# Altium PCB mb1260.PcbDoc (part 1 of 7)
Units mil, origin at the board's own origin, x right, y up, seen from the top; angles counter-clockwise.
Board outline 3189.01 x 3818.89 mil, 6 copper layers (TOP, L2_GND, L3_VCC, L4_SIG, L5_GND, BOTTOM), stack 62.2 mil thick; 308 components, 287 nets, 1220 pads, 851 vias.
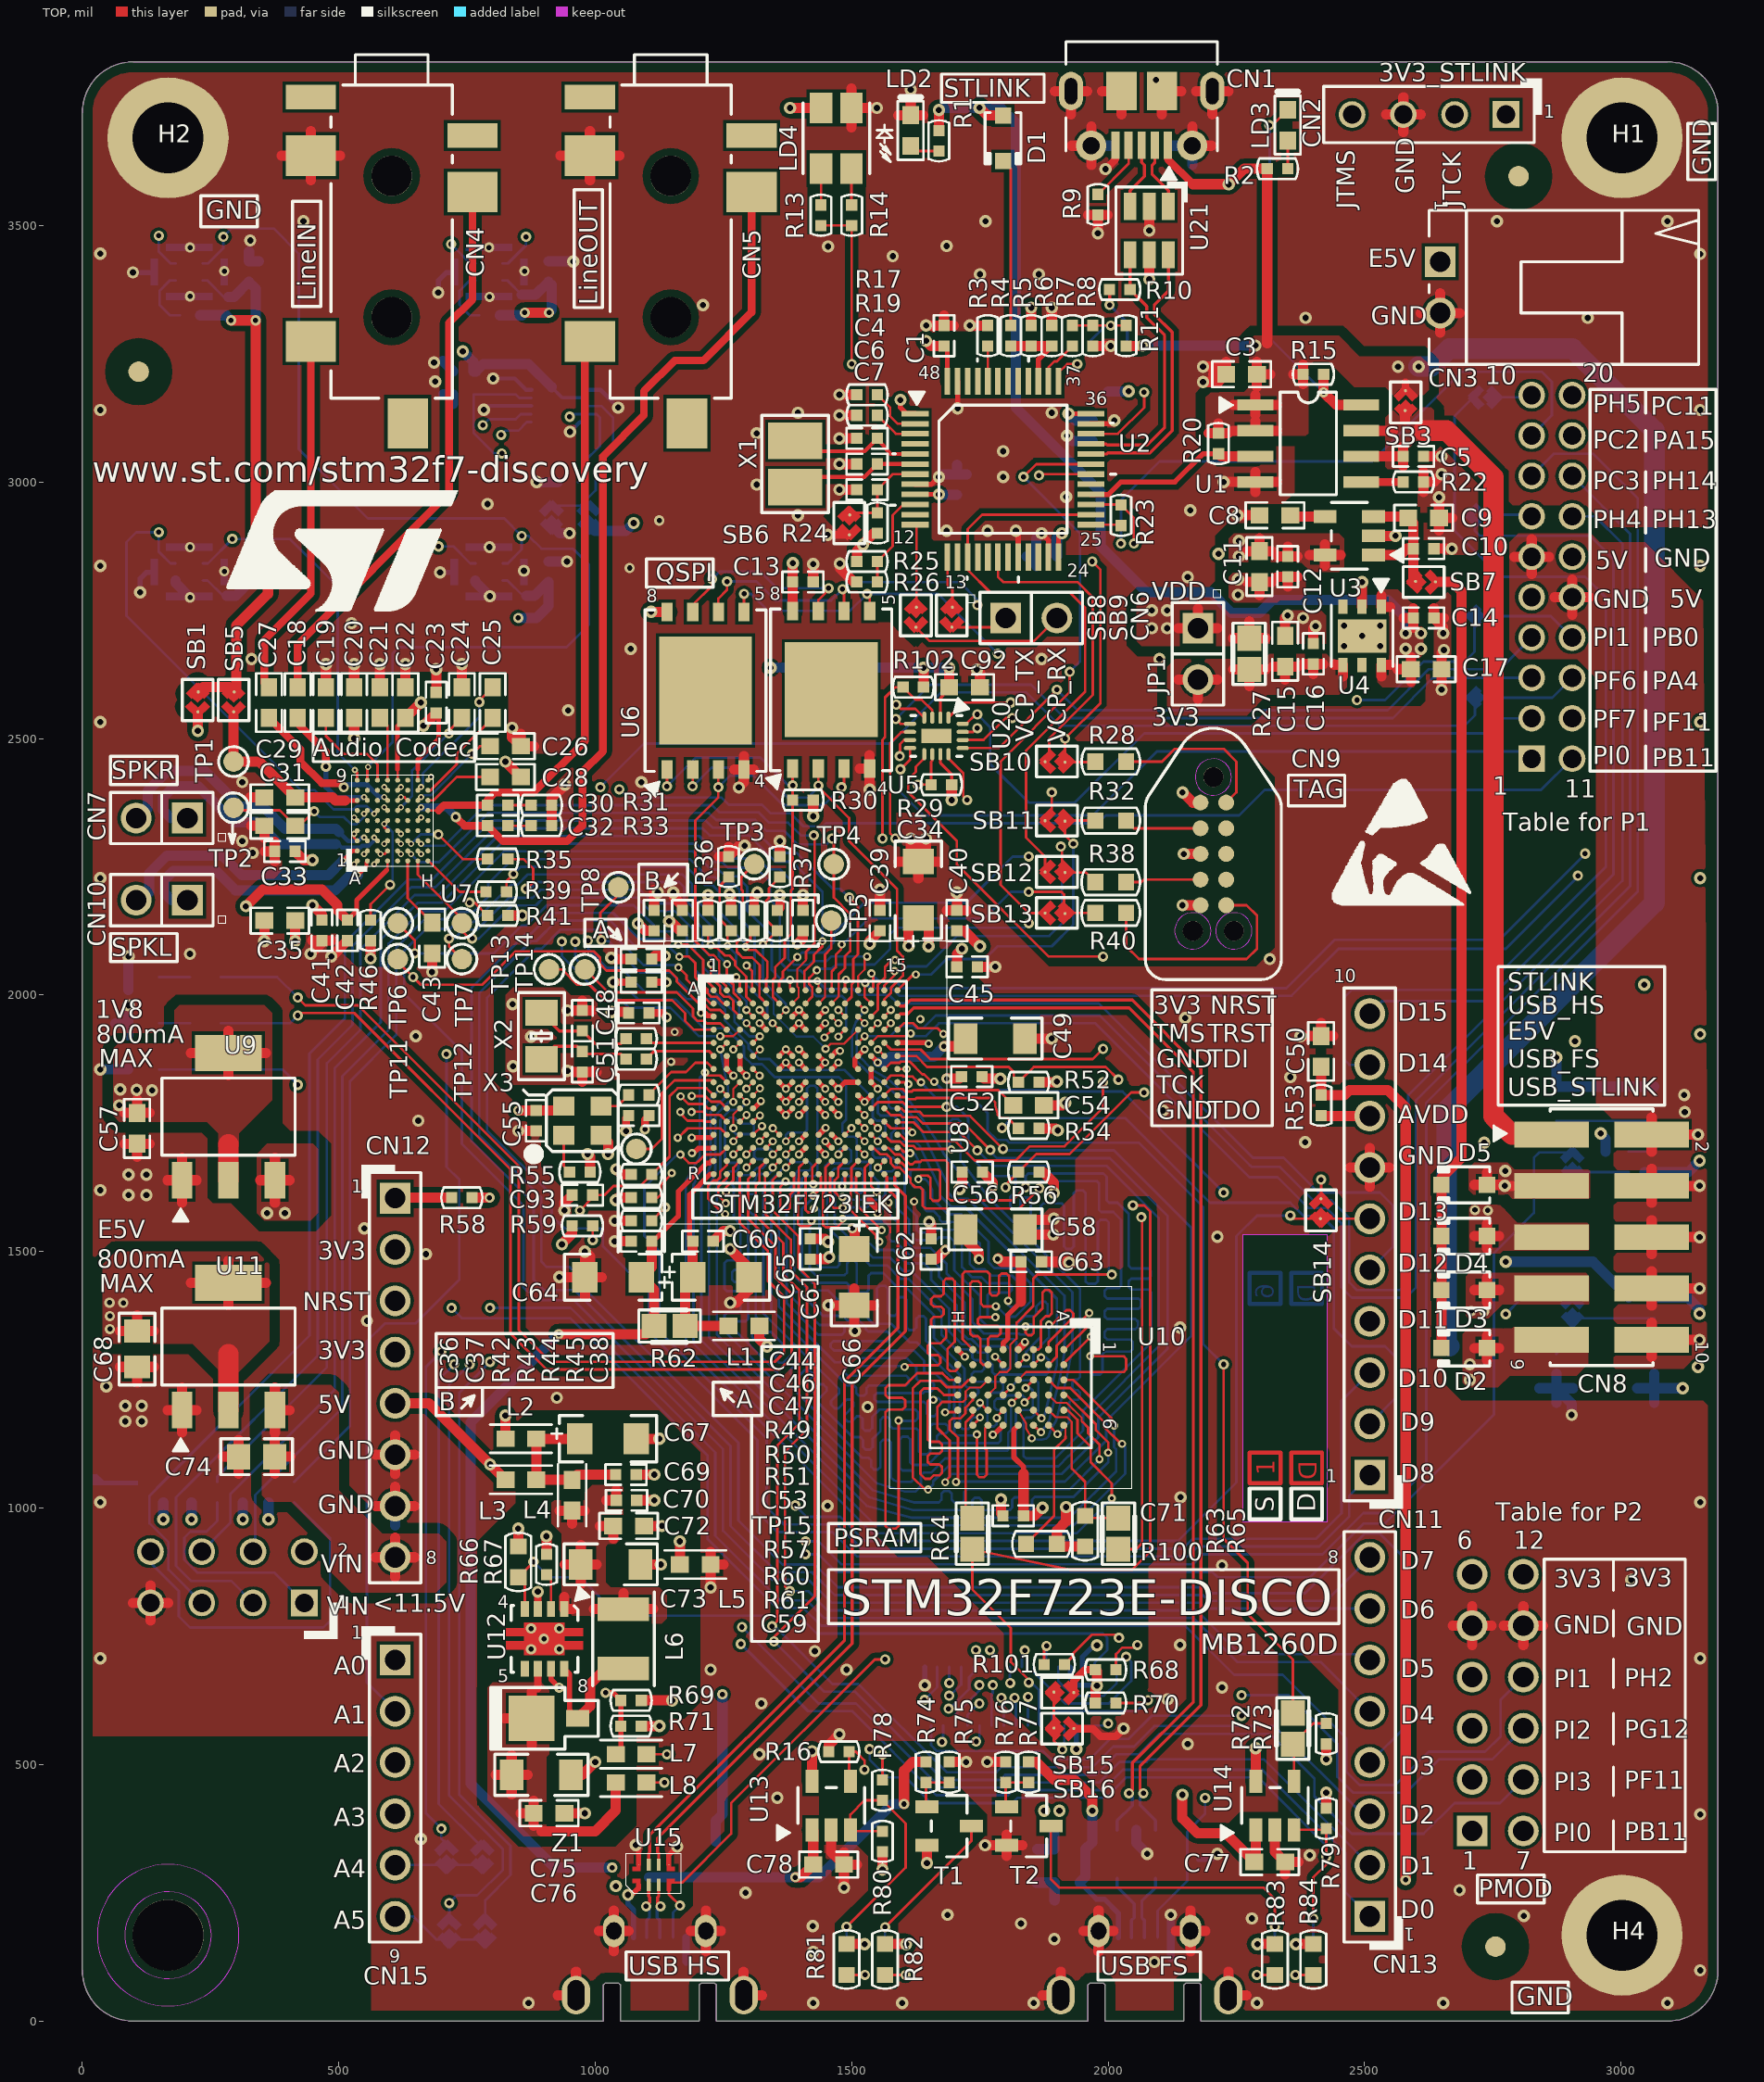
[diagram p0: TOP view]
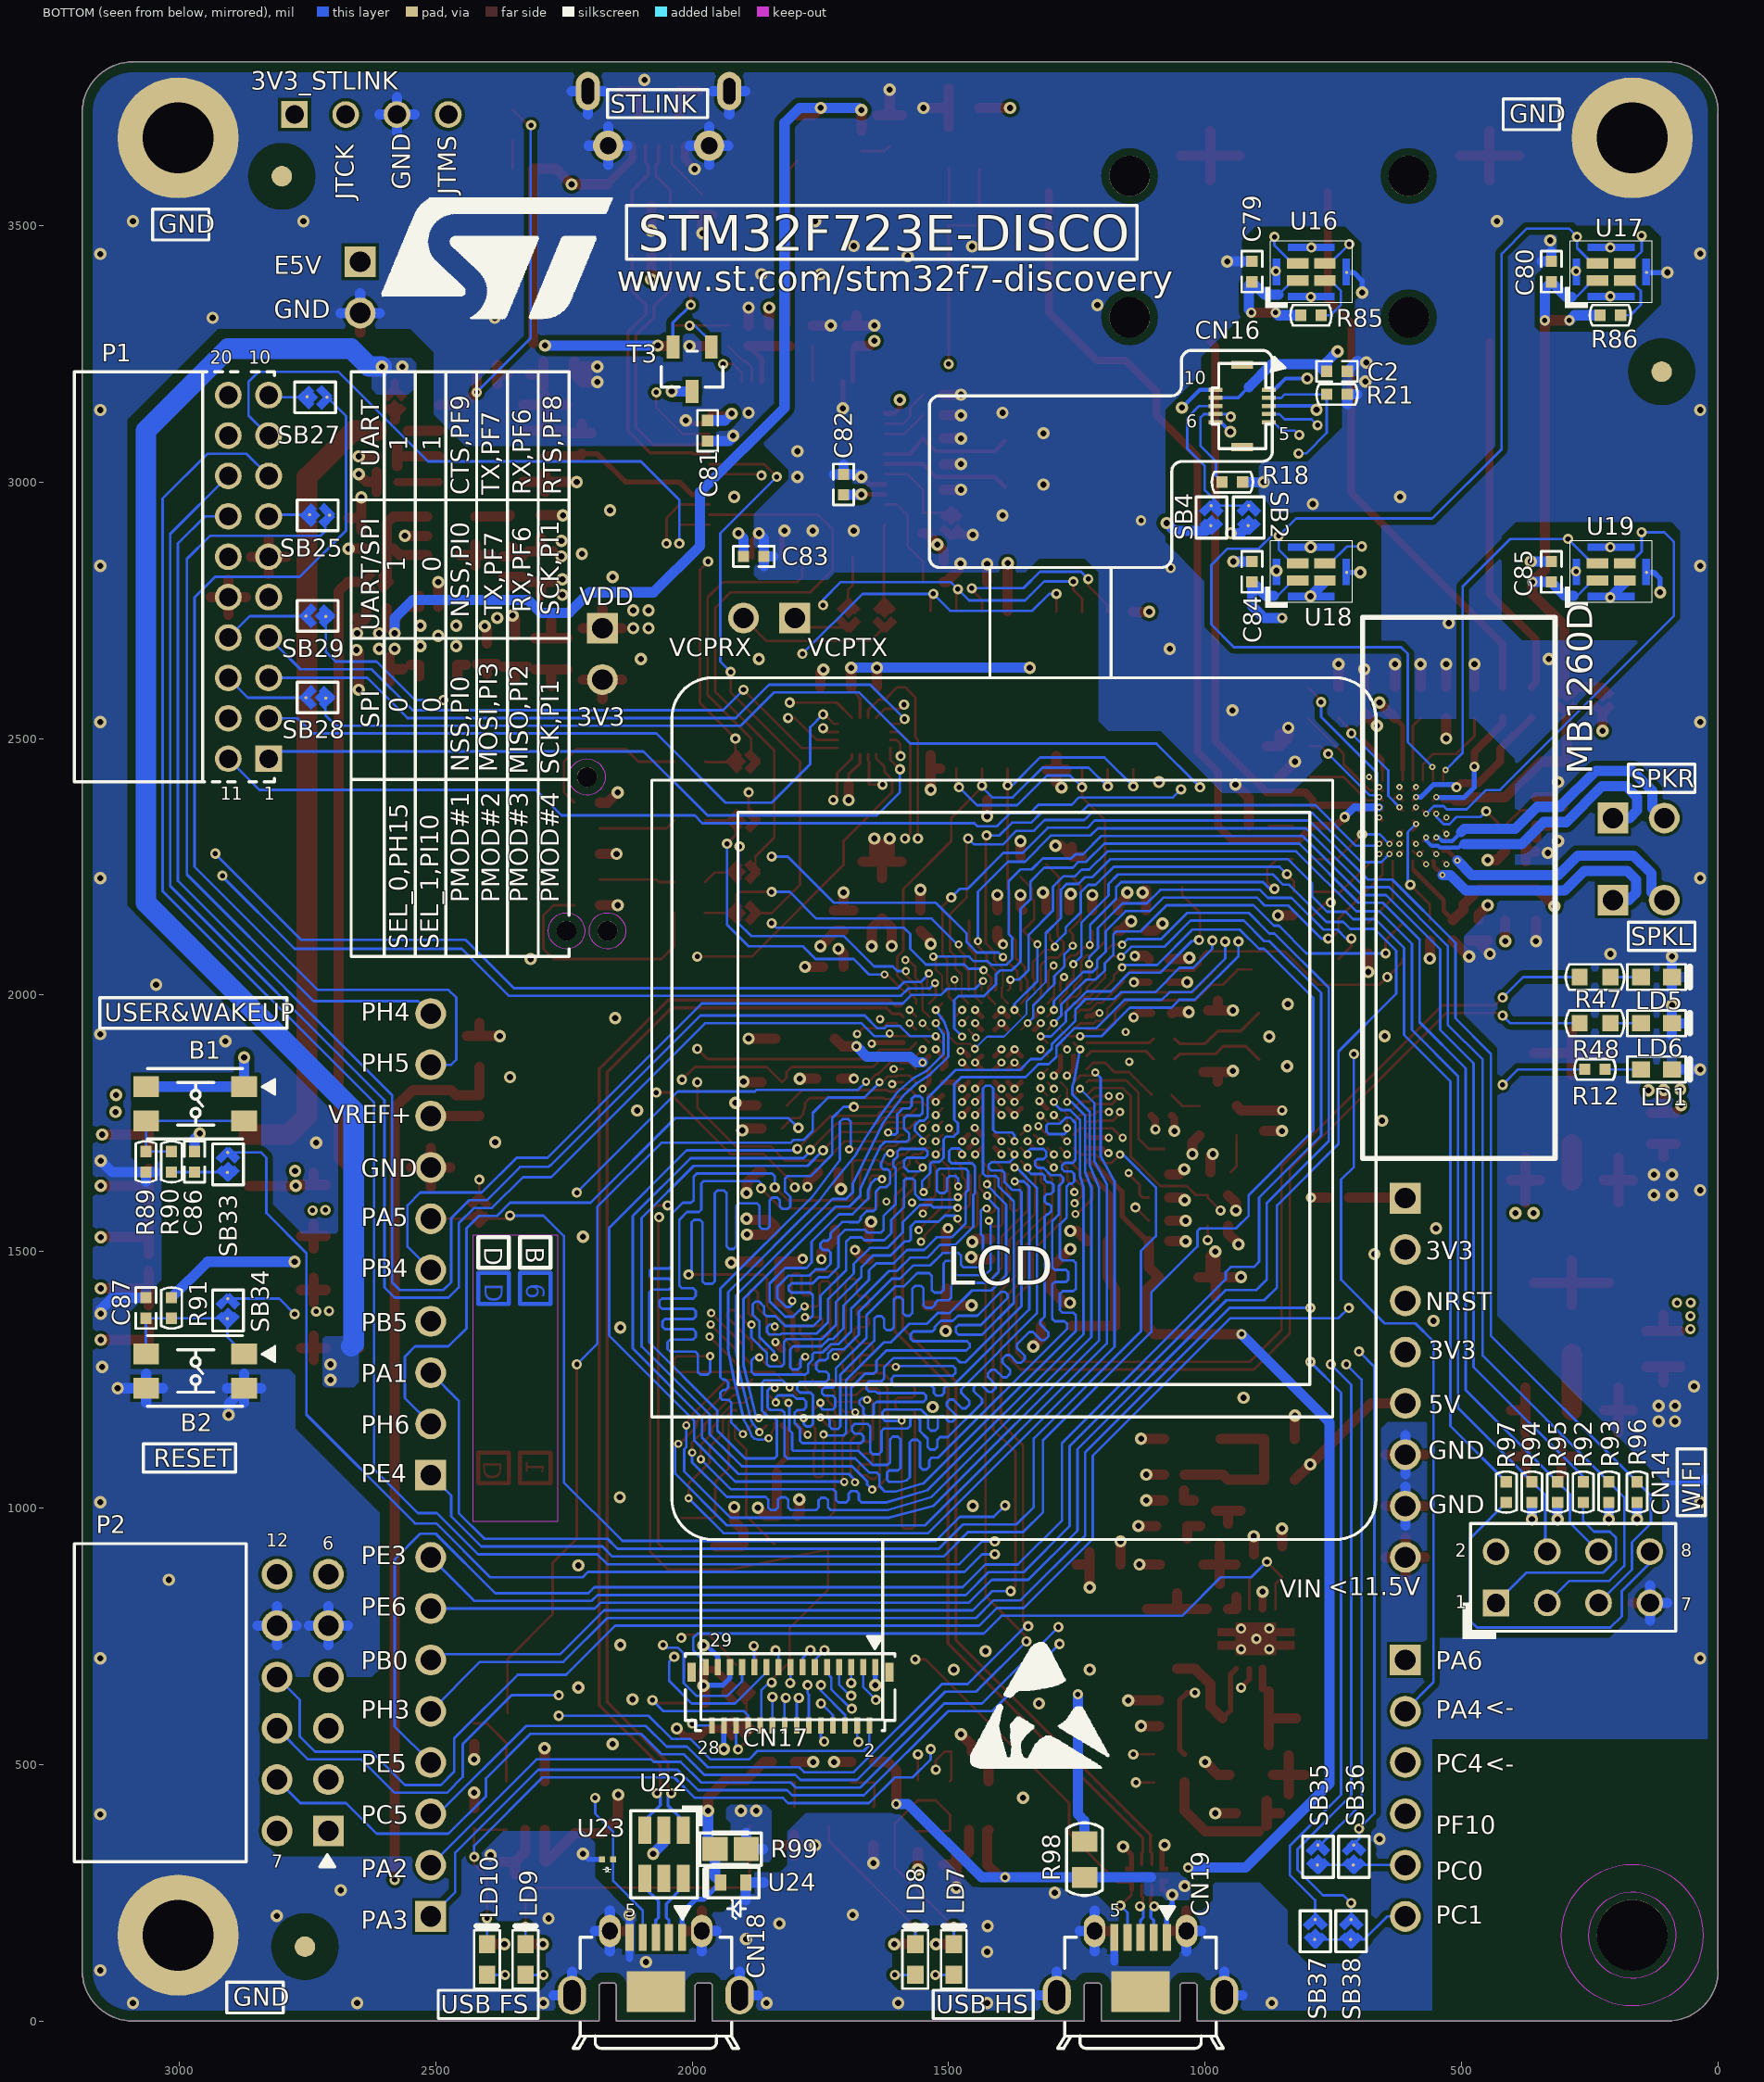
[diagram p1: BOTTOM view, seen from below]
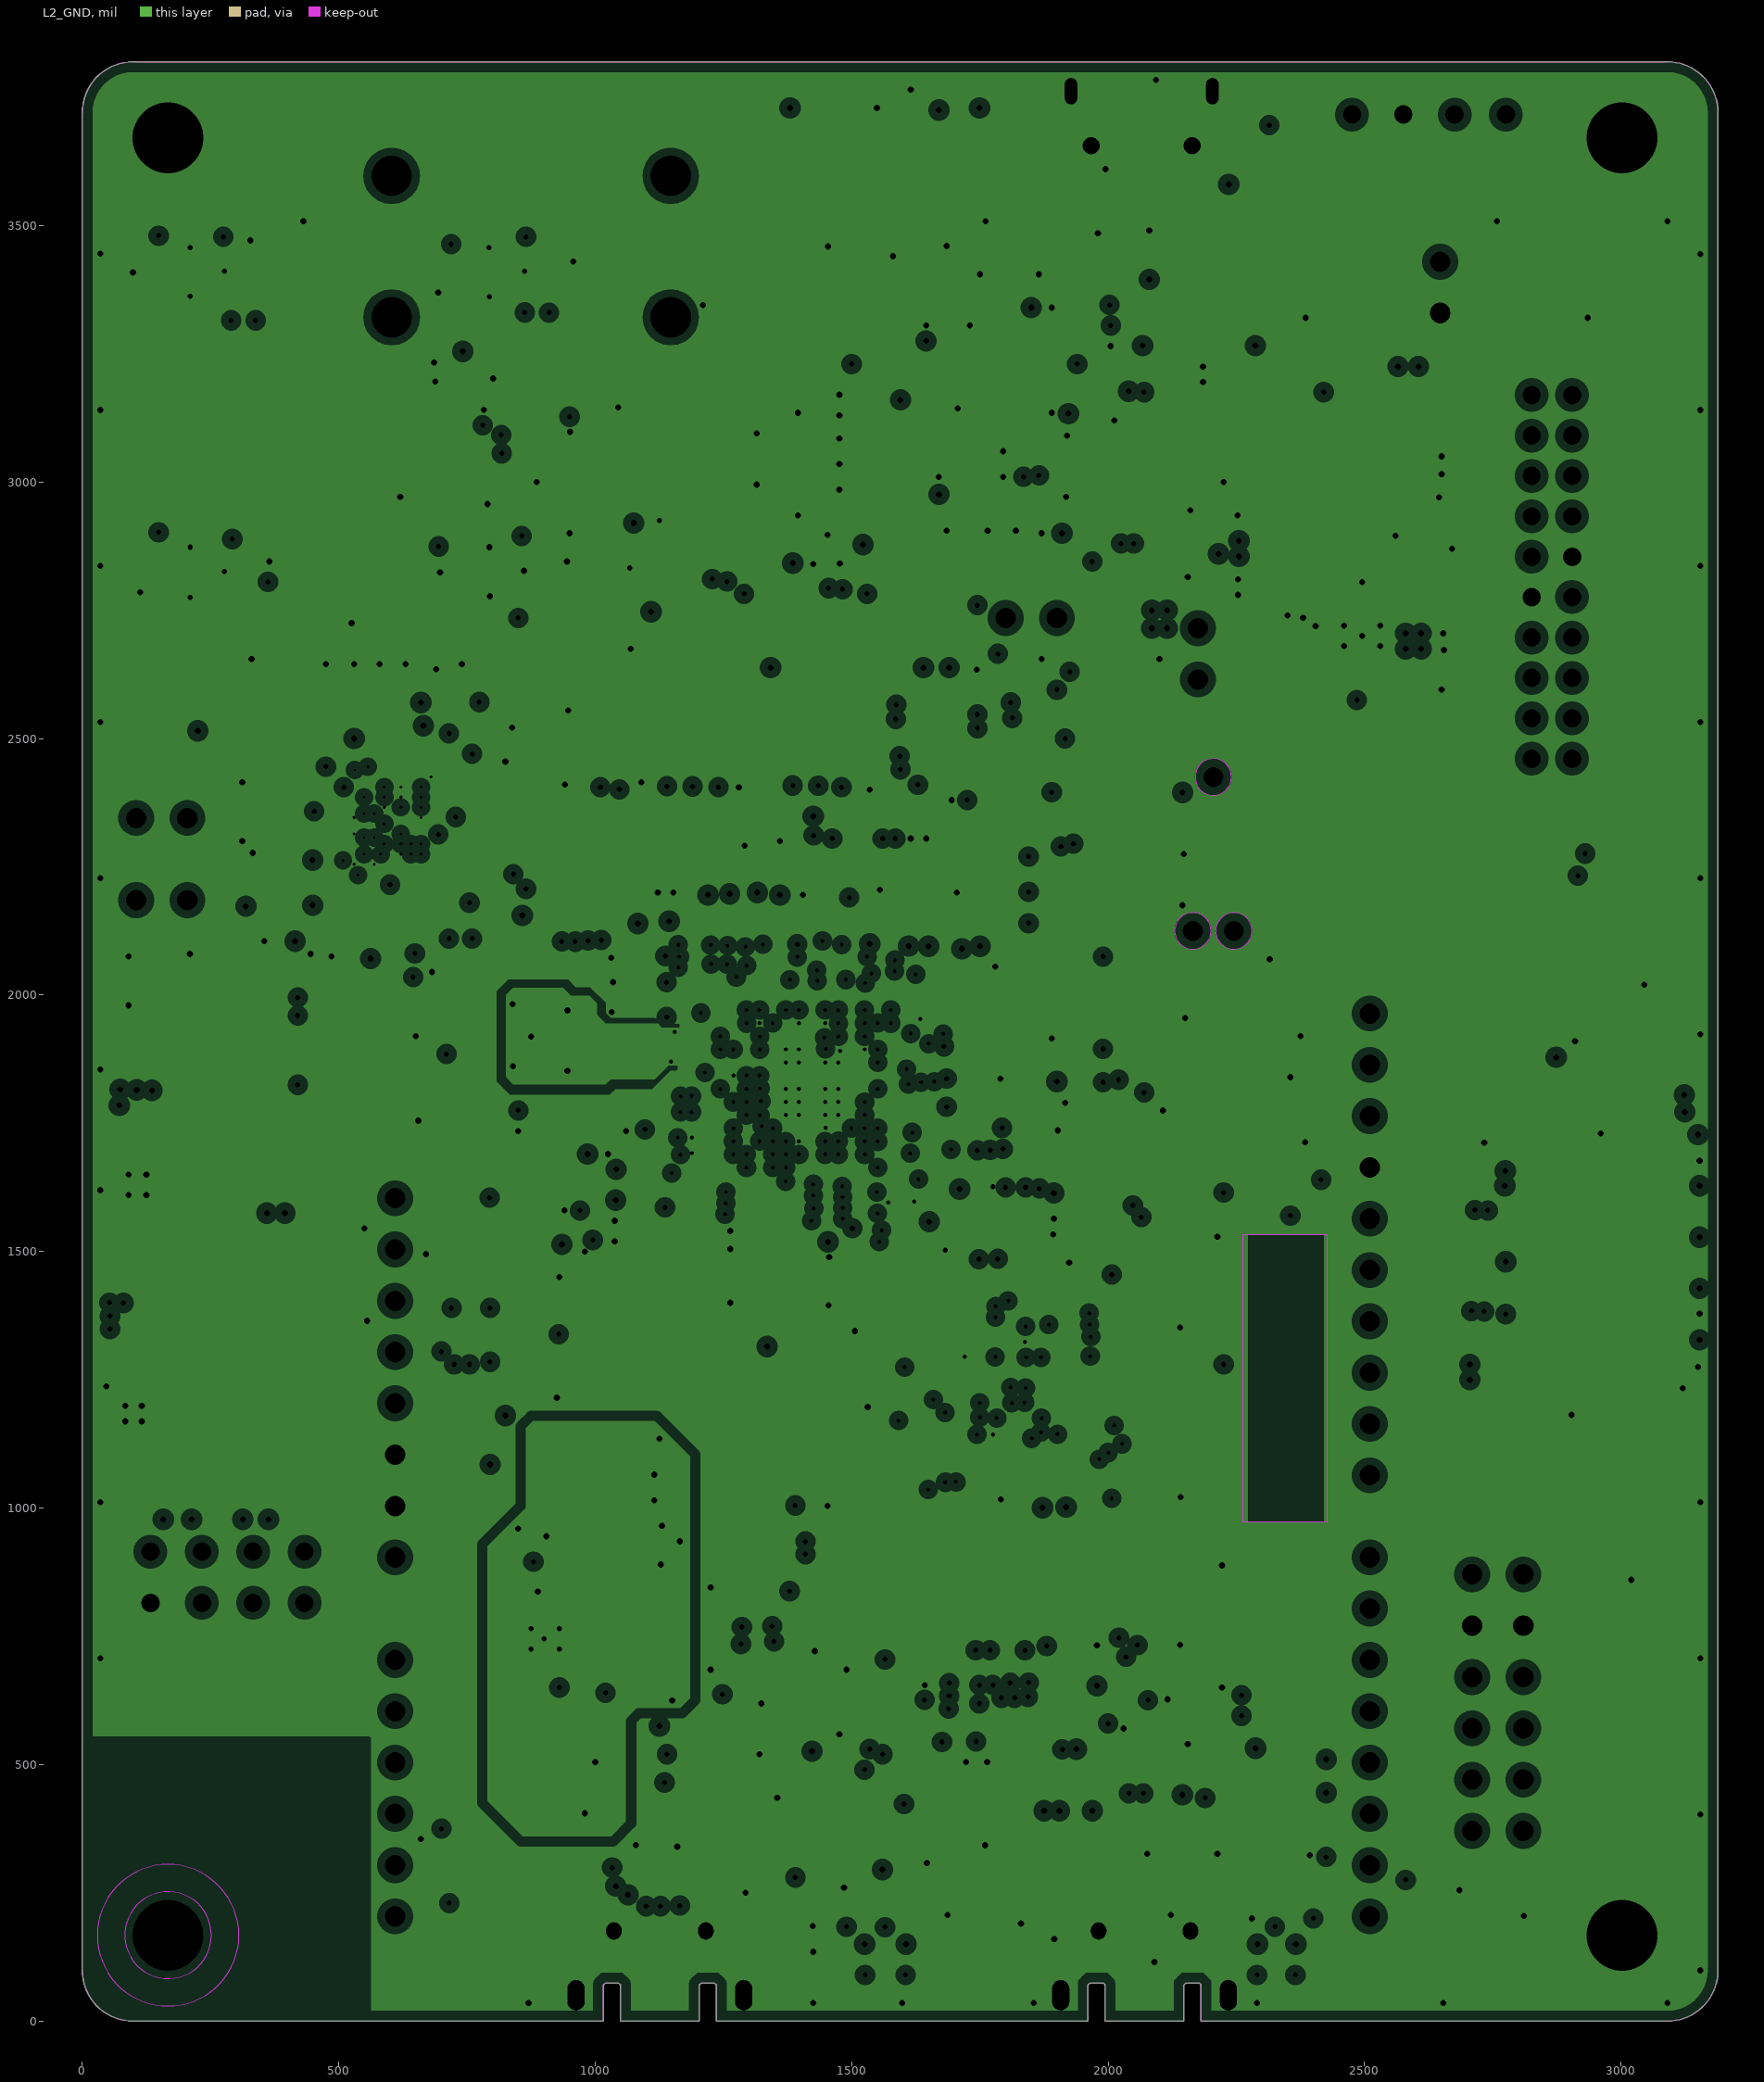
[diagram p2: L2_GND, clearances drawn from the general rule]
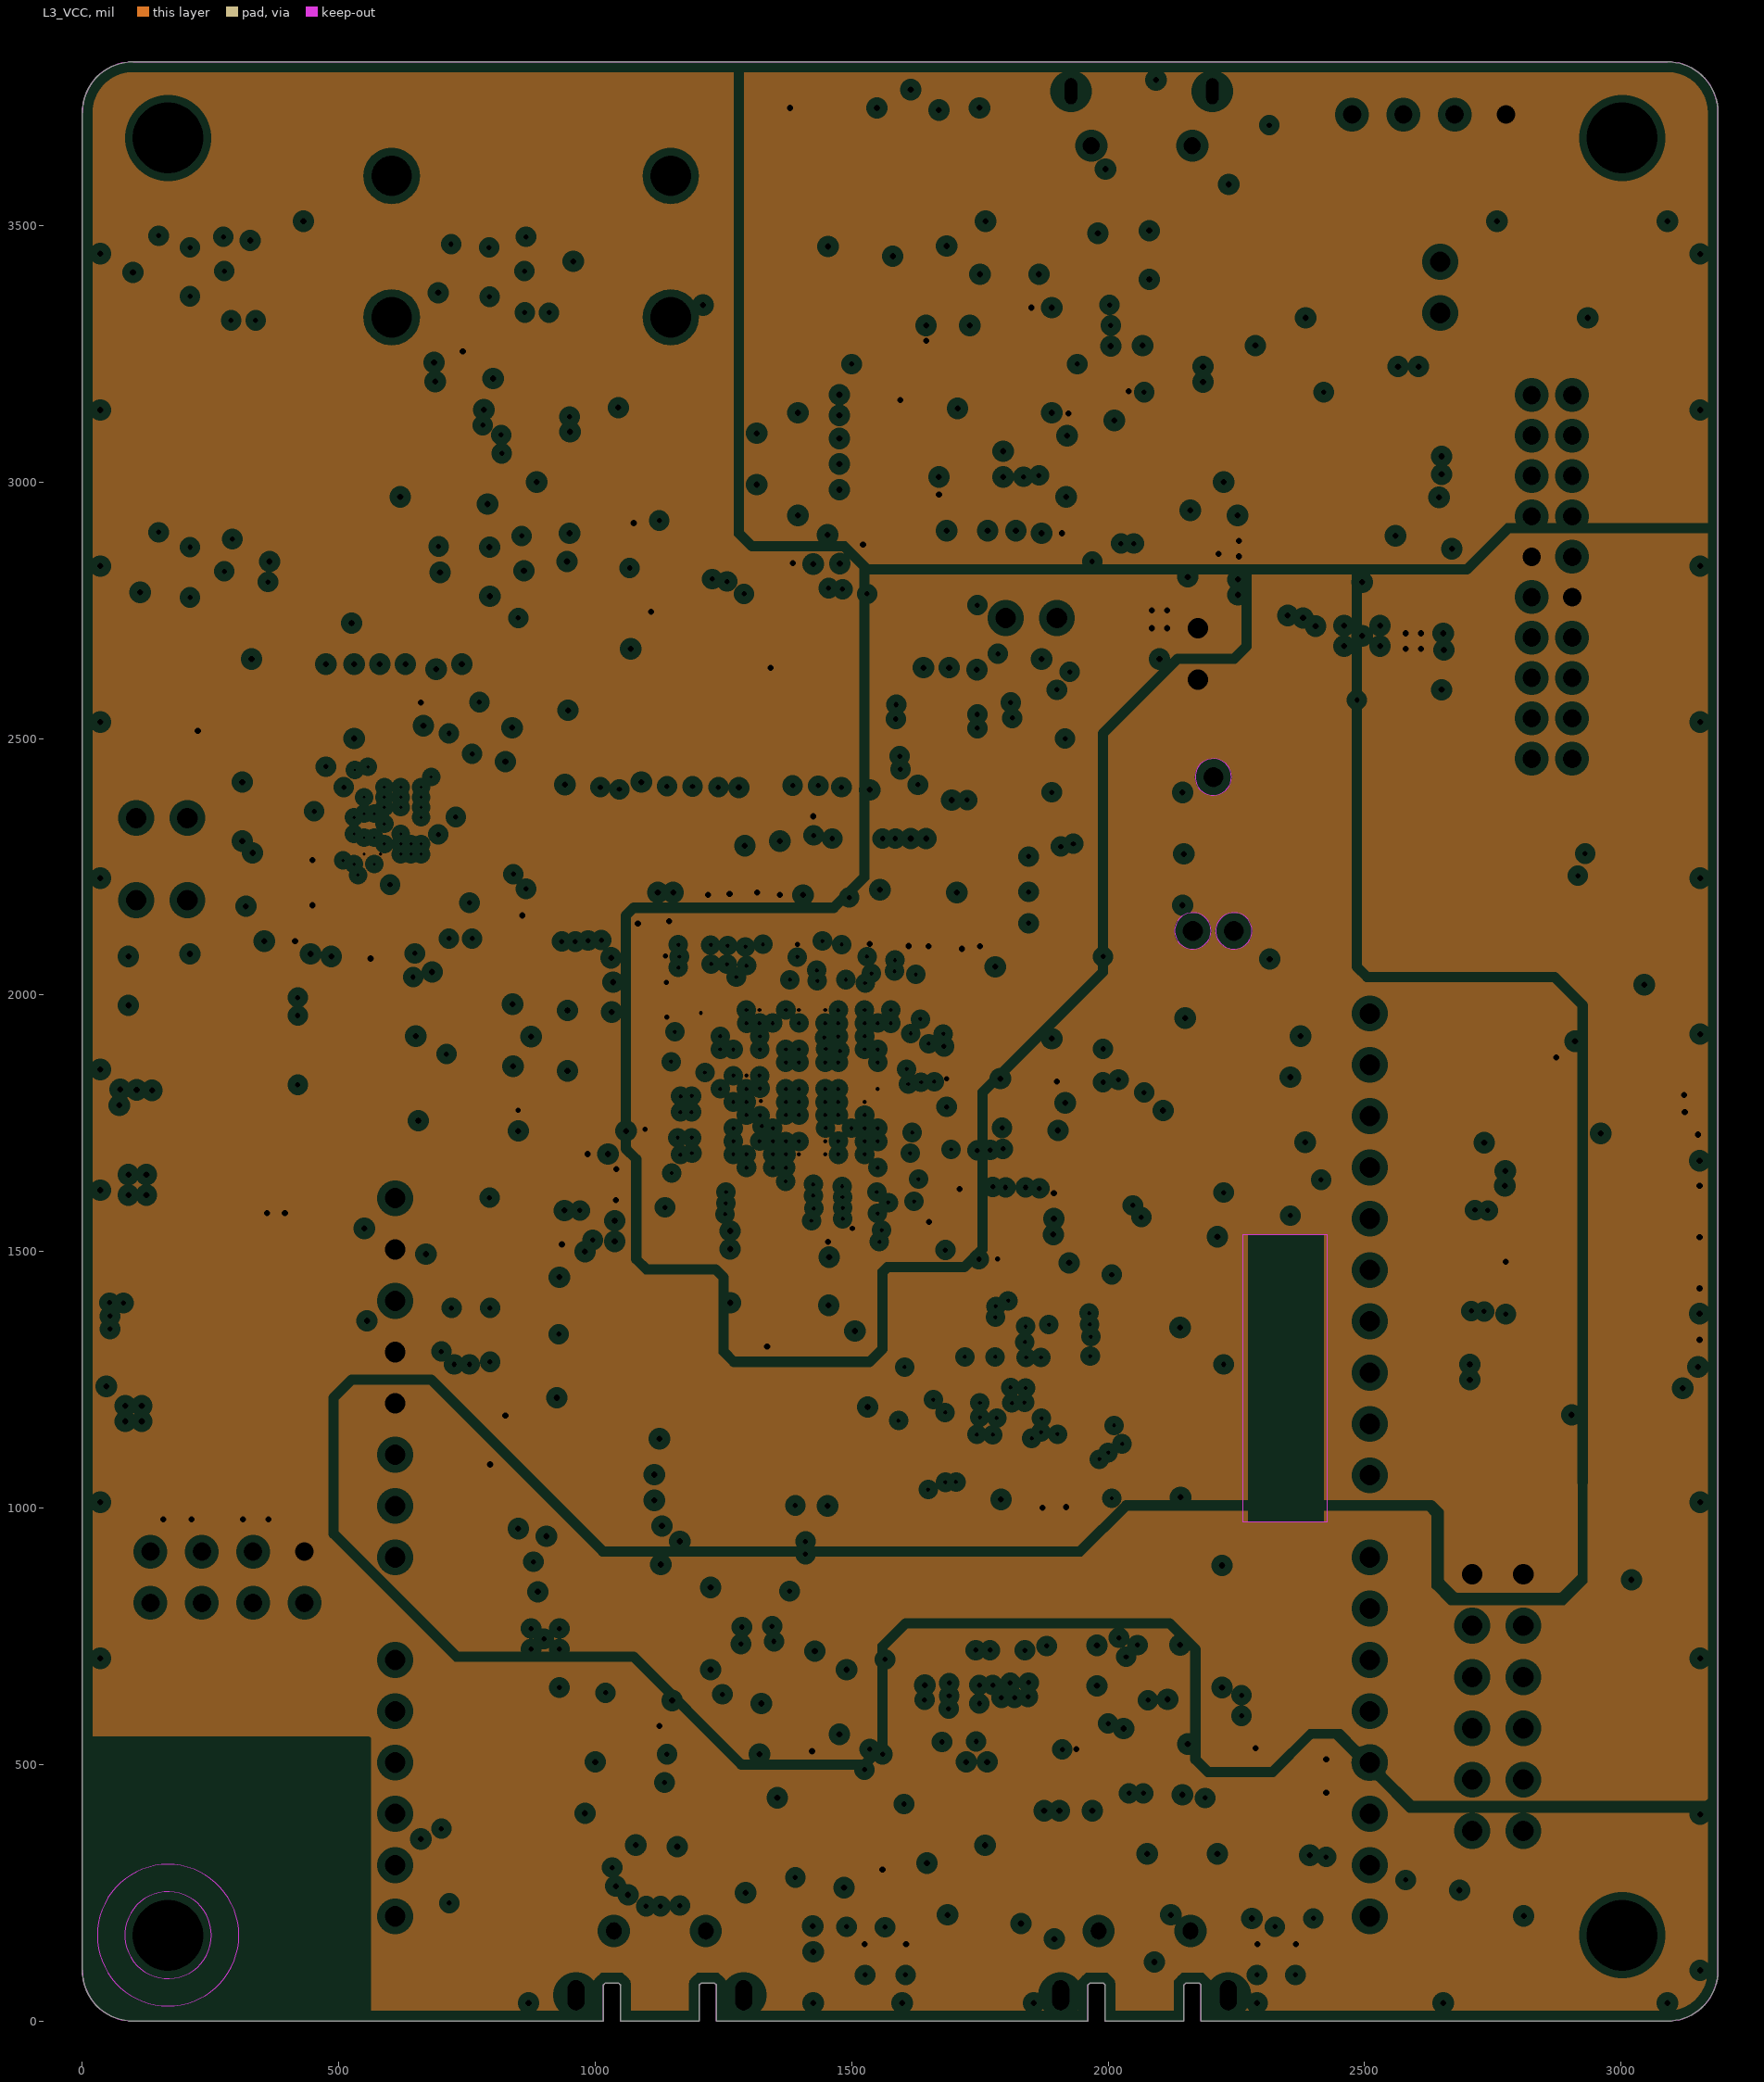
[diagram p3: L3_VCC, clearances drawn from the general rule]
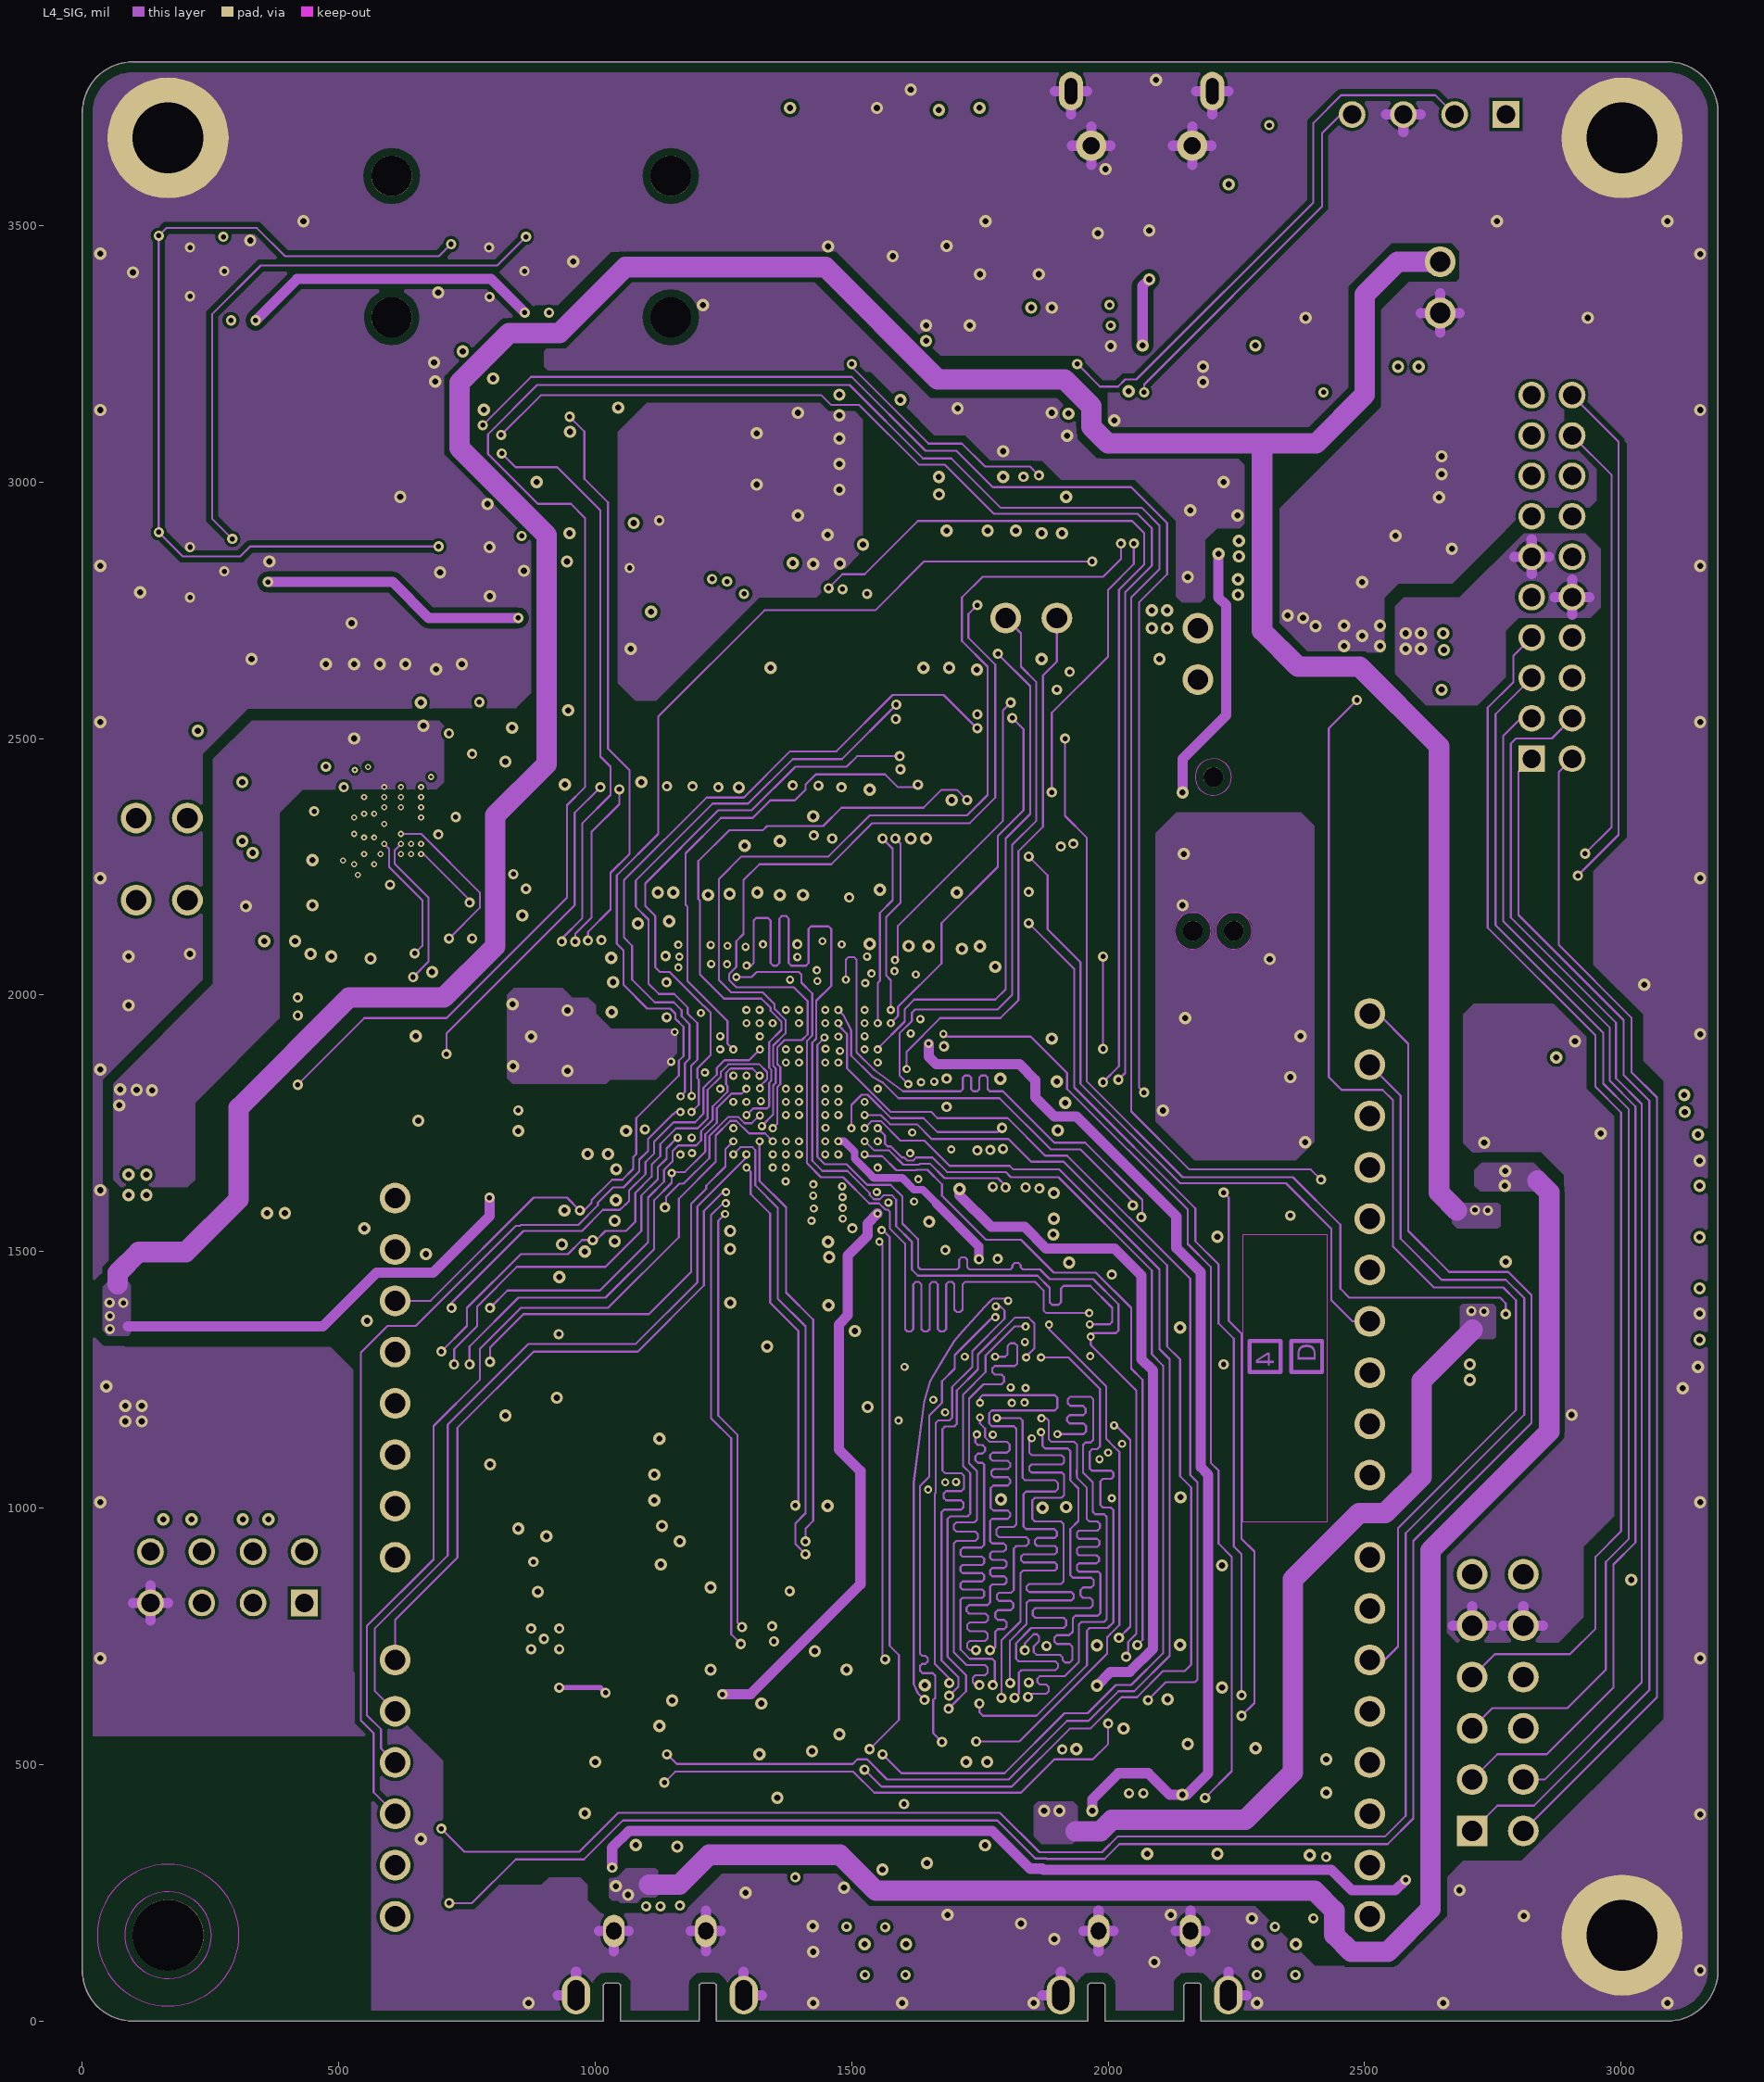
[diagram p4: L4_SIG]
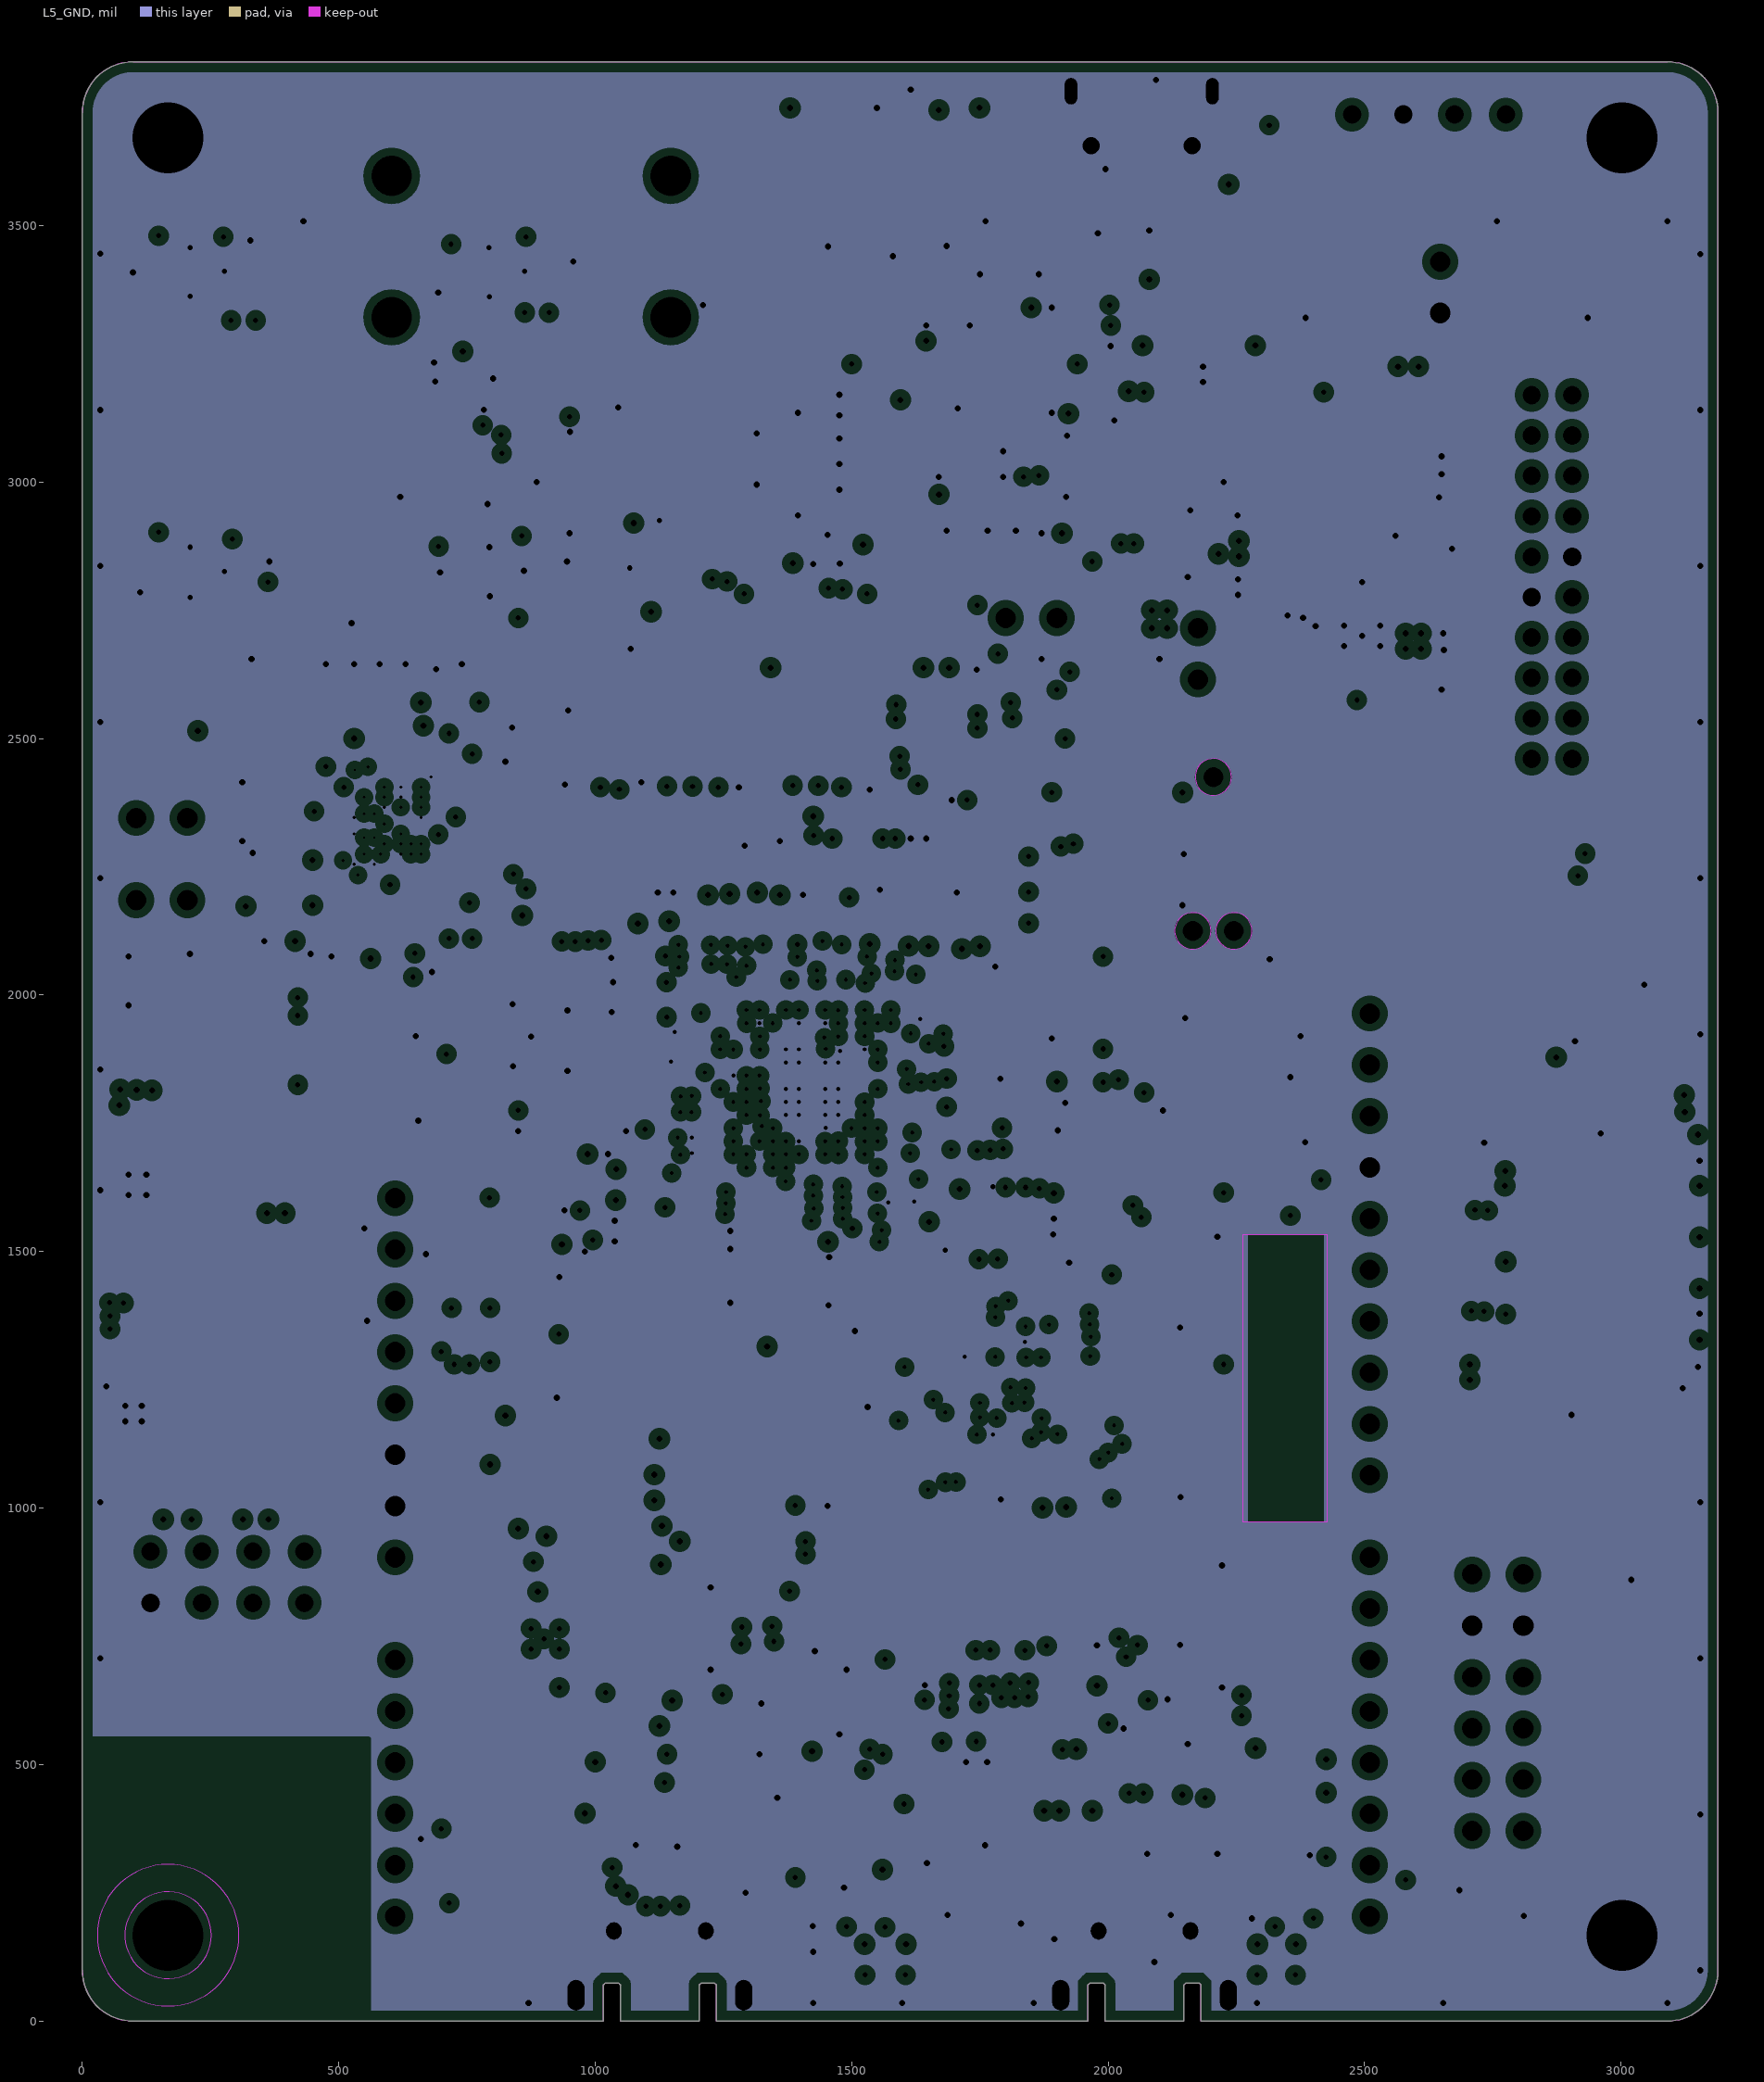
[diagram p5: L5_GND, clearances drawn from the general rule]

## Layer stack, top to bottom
Top Solder: solder mask 0.6, Solder Resist, Dk 3.5
TOP: signal copper 1.8
Dielectric 1: core 3.9, FR-4, Dk 4.3
L2_GND: plane copper 1.2, net (Multiple Nets)
Dielectric2: core 4, FR-4, Dk 4.3
L3_VCC: plane copper 1.2, net (Multiple Nets)
Dielectric3: core 38, FR-4, Dk 4.3
L4_SIG: signal copper 1.2
Dielectric4: core 4, FR-4, Dk 4.3
L5_GND: plane copper 1.2, net GND
Dielectric5: core 3.9, FR-4, Dk 4.3
BOTTOM: signal copper 1.8
Bottom Solder: solder mask 0.6, Solder Resist, Dk 3.5

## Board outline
98.82,0 1015.74,0 1015.74,70.28 1019.68,74.22 1045.27,74.22 1049.21,70.28 1049.21,0 1202.75,0 1202.75,70.28 1206.69,74.22 1232.28,74.22 1236.22,70.28 1236.22,0 1960.63,0 1960.63,70.28 1964.57,74.22 1990.16,74.22 1994.1,70.28 1994.1,0 2147.64,0 2147.64,70.28 2151.58,74.22 2177.17,74.22 2181.11,70.28 2181.11,0 3090.19,0 ccw(c3090.19,98.82) 3189.01,98.82 3189.01,3720.07 ccw(c3090.19,3720.07) 3090.19,3818.89 98.82,3818.89 ccw(c98.82,3720.07) 0,3720.07 0,98.82 ccw(c98.82,98.82)

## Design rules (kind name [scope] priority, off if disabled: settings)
BoardOutlineClearance [All] p1: gap=20 ignorepadtopadclearanceinfootprint=FALSE
Clearance Clearance_chevron [HasFootprint('JP2_SMD')] p1: gap=5 ignorepadtopadclearanceinfootprint=TRUE except(0: Arc-Hole Track-Hole SMDPad-Hole THPad-Hole Via-Hole Fill-Hole Poly-Hole Region-Hole Text-Hole; 3: Poly-Poly Region-Region; 6: SMDPad-Fill SMDPad-Poly SMDPad-Region THPad-Fill THPad-Poly THPad-Region Via-Fill Via-Poly Via-Region Fill-Text Poly-Text Region-Text; 10: Arc-Arc Arc-Track Arc-Fill Arc-Poly Arc-Region Track-Track Track-Fill Track-Poly Track-Region; 20: Fill-Fill Fill-Poly Fill-Region Poly-Region)
Clearance Clearance_U15 [TouchesRoom('RoomDefinition_6')] p2: gap=5 ignorepadtopadclearanceinfootprint=TRUE except(0: Arc-Hole Track-Hole SMDPad-Hole THPad-Hole Via-Hole Fill-Hole Poly-Hole Region-Hole Text-Hole; 3: Fill-Fill Fill-Poly Fill-Region Poly-Poly Poly-Region Region-Region; 6: SMDPad-Fill SMDPad-Poly SMDPad-Region THPad-Fill THPad-Poly THPad-Region Via-Fill Via-Poly Via-Region Fill-Text Poly-Text Region-Text; 10: Arc-Arc Arc-Track Arc-Fill Arc-Poly Arc-Region Track-Track Track-Fill Track-Poly Track-Region)
Clearance Clearance_diff100 [(ObjectKind = 'Track') And (Net = 'NETCN10_2') or  (ObjectKind = 'Track') And (Net = 'NETCN7_2') vs (ObjectKind = 'Track') And (Net = 'NETCN10_1') or (ObjectKind = 'Track') And (Net = 'NETCN7_1')] p3: gap=9.9 ignorepadtopadclearanceinfootprint=FALSE
Clearance Clearance_diff90 [(ObjectKind = 'Track') And (Net Like '*_P') vs (ObjectKind = 'Track') And (Net Like '*_N')] p4: gap=8.9 ignorepadtopadclearanceinfootprint=FALSE except(0: Arc-Hole Track-Hole SMDPad-Hole THPad-Hole Via-Hole Fill-Hole Poly-Hole Region-Hole Text-Hole; 10: Arc-Fill Arc-Poly Arc-Region Track-Fill Track-Poly Track-Region)
Clearance Clearance_BGA0.5 [TouchesRoom('RoomDefinition_BGA0.5')  or  TouchesRoom('RoomDefinition_5')] p5: gap=5 ignorepadtopadclearanceinfootprint=FALSE except(0: Arc-Hole Track-Hole SMDPad-Hole THPad-Hole Via-Hole Fill-Hole Poly-Hole Region-Hole Text-Hole; 3: Arc-SMDPad Arc-THPad Track-SMDPad Track-THPad Via-Via; 3.8: SMDPad-Via THPad-Via; 3.98: Region-Region; 4: Arc-Arc Arc-Track Arc-Via Track-Track Track-Via; 10: Track-Poly; 15: Fill-Fill Fill-Poly Fill-Region Poly-Poly Poly-Region)
Clearance Clearance_Void [(ObjectKind = 'Track') And (Layer = 'TOP') And (ObjectKind = 'Region') vs InPolygon] p6: gap=0.01 ignorepadtopadclearanceinfootprint=FALSE except(0: Arc-Hole Track-Hole SMDPad-Hole THPad-Hole Via-Hole Fill-Hole Poly-Hole Region-Hole Text-Hole)
Clearance Clearance_BGA [TouchesRoom('RoomDefinition_BGA') or TouchesRoom('RoomDefinition_BGA_2')or TouchesRoom('RoomDefinition_1') or TouchesRoom('RoomDefinition_2') or  TouchesRoom('RoomDefinition_3') or TouchesRoom('RoomDefinition_14') or   TouchesRoom('RoomDefinition_15') or TouchesRoom('RoomDefinition_16') or  TouchesRoom('RoomDefinition_17') or TouchesRoom('RoomDefinition_18') or  TouchesRoom('RoomDefinition_19') or TouchesRoom('RoomDefinition_20')] p7: gap=4 ignorepadtopadclearanceinfootprint=FALSE except(0: Arc-Hole Track-Hole SMDPad-Hole THPad-Hole Via-Hole Fill-Hole Poly-Hole Region-Hole Text-Hole; 3.98: Region-Region; 5: Arc-Fill Arc-Poly Arc-Region Track-Fill Track-Poly Track-Region SMDPad-THPad SMDPad-Fill SMDPad-Poly SMDPad-Region THPad-THPad THPad-Fill THPad-Poly THPad-Region Via-Via Via-Fill Via-Poly Via-Region; 15: Fill-Fill Fill-Poly Fill-Region Poly-Poly Poly-Region)
Clearance Clearance_Default_L4 [InNet('No Net') vs OnLayer('L4_SIG')] p8: gap=6 ignorepadtopadclearanceinfootprint=FALSE except(0: Arc-Hole Track-Hole SMDPad-Hole THPad-Hole Via-Hole Fill-Hole Poly-Hole Region-Hole Text-Hole; 5: Arc-SMDPad Arc-THPad Arc-Via Arc-Text Track-SMDPad Track-THPad Track-Via Track-Text SMDPad-SMDPad SMDPad-THPad SMDPad-Via SMDPad-Text THPad-THPad THPad-Via THPad-Text Via-Via Via-Text Text-Text; 8: Arc-Arc Arc-Track Track-Track Region-Region; 20: Fill-Fill Fill-Poly Fill-Region Poly-Poly Poly-Region)
Clearance Clearance_Default [InNet('No Net')] p9: gap=6 ignorepadtopadclearanceinfootprint=FALSE except(0: Arc-Hole Track-Hole SMDPad-Hole THPad-Hole Via-Hole Fill-Hole Poly-Hole Region-Hole Text-Hole; 5: Arc-SMDPad Arc-THPad Arc-Via Arc-Text Track-SMDPad Track-THPad Track-Via Track-Text SMDPad-SMDPad SMDPad-THPad SMDPad-Via SMDPad-Text THPad-THPad THPad-Via THPad-Text Via-Via Via-Text Text-Text; 7.1: Region-Region; 10: Arc-Arc Arc-Track Track-Track; 20: Fill-Fill Fill-Poly Fill-Region Poly-Poly Poly-Region)
Clearance Clearance_2W_L3 [OnLayer('L3_VCC')and not (OnLayer('Keep-Out Layer')) vs OnLayer('L3_VCC')and not (OnLayer('Keep-Out Layer'))] p10: gap=5 ignorepadtopadclearanceinfootprint=FALSE except(0: Arc-Hole Track-Hole SMDPad-Hole THPad-Hole Via-Hole Fill-Hole Poly-Hole Region-Hole Text-Hole; 6: SMDPad-Fill SMDPad-Poly SMDPad-Region THPad-Fill THPad-Poly THPad-Region Via-Fill Via-Poly Via-Region Fill-Text Poly-Text Region-Text; 8: Arc-Arc Arc-Track Arc-Fill Arc-Poly Arc-Region Track-Track Track-Fill Track-Poly Track-Region Region-Region; 20: Fill-Fill Fill-Poly Fill-Region Poly-Poly Poly-Region)
Clearance Clearance_2W_L4 [OnLayer('L4_SIG')   and not (OnLayer('Keep-Out Layer')) vs OnLayer('L4_SIG')   and not (OnLayer('Keep-Out Layer'))] p11: gap=5 ignorepadtopadclearanceinfootprint=FALSE except(0: Arc-Hole Track-Hole SMDPad-Hole THPad-Hole Via-Hole Fill-Hole Poly-Hole Region-Hole Text-Hole; 6: SMDPad-Fill SMDPad-Poly SMDPad-Region THPad-Fill THPad-Poly THPad-Region Via-Fill Via-Poly Via-Region Fill-Text Poly-Text Region-Text; 8: Arc-Arc Arc-Track Track-Track Region-Region; 10: Arc-Fill Arc-Poly Arc-Region Track-Fill Track-Poly Track-Region; 20: Fill-Fill Fill-Poly Fill-Region Poly-Poly Poly-Region)
Clearance Clearance_2W [All and not (OnLayer('Keep-Out Layer')) vs All and not (OnLayer('Keep-Out Layer'))] p12: gap=5 ignorepadtopadclearanceinfootprint=FALSE except(0: Arc-Hole Track-Hole SMDPad-Hole THPad-Hole Via-Hole Fill-Hole Poly-Hole Region-Hole Text-Hole; 6: SMDPad-Fill SMDPad-Poly SMDPad-Region THPad-Fill THPad-Poly THPad-Region Via-Fill Via-Poly Via-Region Fill-Text Poly-Text Region-Text; 10: Arc-Arc Arc-Track Arc-Fill Arc-Poly Arc-Region Track-Track Track-Fill Track-Poly Track-Region; 20: Fill-Fill Fill-Poly Fill-Region Poly-Poly Poly-Region Region-Region)
ComponentClearance [All] p1: gap=0 collisioncheckmode=3 verticalgap=0 showdistances=FALSE
DiffPairsRouting DiffPairsRouting_100Ohm [InDifferentialPairClass('100ohms')] p1: maxlimit=10.9 minlimit=9.9 mostfreqgap=10.9 toplayer_maxgap=9.9 toplayer_prefgap=9.9 toplayer_minwidth=5.1 toplayer_maxwidth=20 toplayer_prefwidth=5.1 midlayer1_mingap=10.9 midlayer1_minwidth=4.1 midlayer1_maxwidth=20 midlayer1_prefwidth=4.1 bottomlayer_maxgap=9.9 bottomlayer_prefgap=9.9 bottomlayer_minwidth=5.1 bottomlayer_maxwidth=20 bottomlayer_prefwidth=5.1 maxuncoupledlength=500
DiffPairsRouting DiffPairsRouting_90Ohm [InDifferentialPairClass('90ohms')] p2: maxlimit=9.9 minlimit=8.9 mostfreqgap=9.9 toplayer_maxgap=8.9 toplayer_prefgap=8.9 toplayer_minwidth=6.1 toplayer_maxwidth=6.1 toplayer_prefwidth=6.1 midlayer1_mingap=9.9 midlayer1_minwidth=5.1 midlayer1_maxwidth=5.1 midlayer1_prefwidth=5.1 bottomlayer_maxgap=8.9 bottomlayer_prefgap=8.9 bottomlayer_minwidth=6.1 bottomlayer_maxwidth=6.1 bottomlayer_prefwidth=6.1 maxuncoupledlength=500
HoleSize [All] p1: absolutevalues=TRUE maxlimit=138 minlimit=6 maxpercent=80.000 minpercent=20.000
MaxMinImpedance "Schematic Impedance Constraint" [InNet('PSRAM_NBL0')] p1: minimum=40,00 maximum=60,00
PlaneClearance PlaneClearance_BGA0.5 [(ObjectKind = 'Via') And (AsMils(HoleDiameter) = 6)] p1: clearance=6
PlaneClearance PlaneClearance_BGA [(ObjectKind = 'Via') And (AsMils(HoleDiameter) = 8)] p2: clearance=8.89
PlaneClearance PlaneClearance_via [(ObjectKind = 'Via')] p3: clearance=10
PlaneClearance [All] p4: clearance=15
PlaneConnect PlaneConnect_MECA [(Component = 'H4') or (Component = 'H1') or (Component = 'H2')] p1: planeconnectstyle=Relief reliefexpansion=2 reliefentries=4 reliefconductorwidth=30 reliefairgap=7
PlaneConnect PlaneConnect_Vias [isvia] p2: planeconnectstyle=Direct reliefexpansion=20 reliefentries=4 reliefconductorwidth=10 reliefairgap=10
PlaneConnect PlaneConnect_HOLE [(ObjectKind = 'Pad') And (Name = 'CN18-9') or (ObjectKind = 'Pad') And (Name = 'CN18-8') or   (ObjectKind = 'Pad') And (Name = 'CN19-9') or   (ObjectKind = 'Pad') And (Name = 'CN19-8')] p3: planeconnectstyle=Relief reliefexpansion=20 reliefentries=4 reliefconductorwidth=20 reliefairgap=7
PlaneConnect [All] p4: planeconnectstyle=Relief reliefexpansion=7.5 reliefentries=4 reliefconductorwidth=15 reliefairgap=7
PolygonConnect PolygonConnect_Hole [(Component = 'H4') or (Component = 'H1') or (Component = 'H2')] p1: connectstyle=Direct reliefconductorwidth=10 reliefentries=4 polygonreliefangle="90 Angle" airgapwidth=10
PolygonConnect PolygonConnect_USB10 [(ObjectKind = 'Pad') And (Name = 'CN19-10') or (ObjectKind = 'Pad') And (Name = 'CN18-10')] p2: connectstyle=Direct reliefconductorwidth=10 reliefentries=4 polygonreliefangle="90 Angle" airgapwidth=10
PolygonConnect PolygonConnect_CN8 [(ObjectKind = 'Pad') And (Name = 'CN8-3') or (ObjectKind = 'Pad') And (Name = 'CN8-5') or (ObjectKind = 'Pad') And (Name = 'CN8-7') or (ObjectKind = 'Pad') And (Name = 'CN8-9')] p3: connectstyle=Direct reliefconductorwidth=10 reliefentries=4 polygonreliefangle="90 Angle" airgapwidth=10
PolygonConnect PolygonConnect_Vias [All vs isvia] p4: connectstyle=Direct reliefconductorwidth=10 reliefentries=4 polygonreliefangle="90 Angle" airgapwidth=10
PolygonConnect [All] p5: connectstyle=Relief reliefconductorwidth=20 reliefentries=4 polygonreliefangle="90 Angle" airgapwidth=6
RoomDefinition RoomDefinition_5 [All] p1: confinementstyle=ConfineOut formatcopy=TRUE lockcomponents=FALSE outline 517.97,2442 689.03,2442 689.03,2246.84 517.97,2246.84
RoomDefinition RoomDefinition_BGA [False] p2: confinementstyle=ConfineIn formatcopy=TRUE lockcomponents=FALSE outline 1200,1631.82 1200,2033.18 1206.82,2040 1360,2040 1390,2070 1505,2070 1535,2040 1615,2040 1615,1970 1640,1945 1640,1670 1615,1645 1615,1630.91 1551.3,1567.2 1547.26,1567.2 1509.46,1605 1226.82,1605
RoomDefinition RoomDefinition_6 [All vs False] p3: confinementstyle=ConfineOut formatcopy=TRUE lockcomponents=FALSE outline 1067.42,296.18 1159.44,296.18 1159.44,274.91 1067.42,274.91
RoomDefinition RoomDefinition_20 [All vs False] p4: confinementstyle=ConfineOut formatcopy=TRUE lockcomponents=FALSE outline 134.34,2879.33 172.34,2879.33 172.34,2837.33 134.34,2837.33
RoomDefinition RoomDefinition_19 [All vs False] p5: confinementstyle=ConfineOut formatcopy=TRUE lockcomponents=FALSE outline 246.34,2880.33 285.34,2880.33 285.34,2768.33 246.34,2768.33
RoomDefinition RoomDefinition_18 [All] p6: confinementstyle=ConfineOut formatcopy=TRUE lockcomponents=FALSE outline 721.34,2875.33 761.34,2875.33 761.34,2837.33 721.34,2837.33
RoomDefinition RoomDefinition_17 [All] p7: confinementstyle=ConfineOut formatcopy=TRUE lockcomponents=FALSE outline 827.34,2880.33 862.34,2880.33 862.34,2771.33 827.34,2771.33
RoomDefinition RoomDefinition_16 [All vs False] p8: confinementstyle=ConfineOut formatcopy=TRUE lockcomponents=FALSE outline 964.34,3178.33 1003.34,3178.33 1003.34,3107.33 964.34,3107.33
RoomDefinition RoomDefinition_15 [All vs False] p9: confinementstyle=ConfineOut formatcopy=TRUE lockcomponents=FALSE outline 843.34,3180.33 885.34,3180.33 885.34,3106.33 843.34,3106.33
RoomDefinition RoomDefinition_14 [All vs False] p10: confinementstyle=ConfineOut formatcopy=TRUE lockcomponents=FALSE outline 831.34,3458.33 870.34,3458.33 870.34,3348.33 831.34,3348.33
RoomDefinition RoomDefinition_3 [All vs False] p11: confinementstyle=ConfineOut formatcopy=TRUE lockcomponents=FALSE outline 724.28,3458.33 758.93,3458.33 758.93,3349.33 724.28,3349.33
RoomDefinition RoomDefinition_2 [All] p12: confinementstyle=ConfineOut formatcopy=TRUE lockcomponents=FALSE outline 243.34,3458.41 279.34,3458.41 279.34,3347.21 243.34,3347.21
RoomDefinition RoomDefinition_1 [All] p13: confinementstyle=ConfineOut formatcopy=TRUE lockcomponents=FALSE outline 143.34,3459.06 175.34,3459.06 175.34,3346.21 143.34,3346.21
RoomDefinition RoomDefinition_BGA_2 [False] p14: confinementstyle=ConfineIn formatcopy=TRUE lockcomponents=FALSE outline 1675,1140 1675,1344.28 1770,1344.28 1785,1359.28 1785,1390 1790,1395 1830,1395 1835,1390 1835,1349.28 1840,1344.28 1950,1344.28 1950,1140 1942,1132 1912,1132 1904,1140
RoomDefinition RoomDefinition_13 [All] p15: confinementstyle=ConfineOut formatcopy=TRUE lockcomponents=FALSE outline 245,3460 281,3460 281,3350 245,3350
RoomDefinition RoomDefinition_4 [All] p16: confinementstyle=ConfineOut formatcopy=TRUE lockcomponents=FALSE outline 830,2880 866,2880 866,2770 830,2770
RoomDefinition RoomDefinition_BGA0.5 [All] p17: confinementstyle=ConfineIn formatcopy=TRUE lockcomponents=FALSE outline 518.78,2246.26 689.01,2246.26 689.01,2437.92 518.78,2437.92
RoomDefinition [All] p18: confinementstyle=ConfineOut formatcopy=TRUE lockcomponents=FALSE outline 1675,1344.28 1770,1344.28 1785,1359.28 1785,1390 1790,1395 1830,1395 1835,1390 1835,1349.28 1840,1344.28 1950,1344.28 1950,1140 1942,1132 1912,1132 1904,1140 1675,1140
RoutingVias [All] p1: holewidth=28 width=50 viastyle="Through Hole" minholewidth=6 minwidth=12 maxholewidth=28 maxwidth=50
SolderMaskExpansion SolderMaskExpansion_via [IsVia] p1: expansion=0 istentingtop=FALSE
SolderMaskExpansion [All] p2: expansion=3 istentingtop=FALSE
Width Width_20Mil [InNet('1V8') or InNet('VDD') or  InNet('NETR76_2') or  InNet('3V3') or  InNet('3V3_ST_LINK') or  InNet('5V_ST_LINK')] p1: maxlimit=100 minlimit=5 preferedwidth=20 minimp=50.000000 maximp=50.000000 favimp=50.000000
Width Width_Default [All] p2: maxlimit=99999 minlimit=4 preferedwidth=5 midlayer1_prefwidth=4 minimp=50.870000 maximp=50.870000 favimp=50.870000
25 further rules are at their usual default settings.

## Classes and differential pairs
differential pair class 100ohms: SPKOUTL SPKOUTR
differential pair class 90ohms: USB_OTGFS USB_OTGFS_CN USB_OTGHS USB_OTGHS_CN USB_STLK USB_STLK_CN
net class QSPI_BK: NETR72_2
net class PSRAM_CRL: LCD_PSRAM_NOE LCD_PSRAM_NWE NETR63_1 PSRAM_NBL0 PSRAM_NBL1
net class PSRAM_ADD: PSRAM_A0 PSRAM_A1 PSRAM_A2 PSRAM_A3 PSRAM_A4 PSRAM_A5 PSRAM_A6 PSRAM_A7 PSRAM_A8 PSRAM_A9 PSRAM_A10 PSRAM_A11 PSRAM_A12 PSRAM_A13 PSRAM_A14 PSRAM_A15 PSRAM_A16 PSRAM_A17
net class LCD_PSRAM_DATA: LCD_PSRAM_D0 LCD_PSRAM_D1 LCD_PSRAM_D2 LCD_PSRAM_D3 LCD_PSRAM_D4 LCD_PSRAM_D5 LCD_PSRAM_D6 LCD_PSRAM_D7 LCD_PSRAM_D8 LCD_PSRAM_D9 LCD_PSRAM_D10 LCD_PSRAM_D11 LCD_PSRAM_D12 LCD_PSRAM_D13 LCD_PSRAM_D14 LCD_PSRAM_D15
net class DATA: NETR10_1 NETR19_2 NETR35_2 NETR39_2
component class "U_Arduino_ Connectors": C50 CN11 CN12 CN13 CN15 LD1 R12 R53 R58 SB14 SB35 SB36 SB37 SB38
component class U_AUDIO: C18 C19 C20 C21 C22 C23 C24 C25 C26 C27 C28 C29 C30 C31 C32 C33 C35 C41 C42 C43 C79 C80 C84 C85 CN4 CN5 CN7 CN10 R31 R33 R35 R39 R41 R46 R85 R86 SB1 SB5 TP1 TP2 U7 U16 U17 U18 U19
component class U_HW_Mechanical_Parts: H1 H2 H4 HW1 HW2 HW3 HW4 HW5 HW6 HW7 HW8 HW9 HW10 HW11
component class U_LCD_FRIDA: C2 C67 C69 C70 C72 C73 C75 C76 CN16 CN17 L2 L3 L4 L5 L6 L7 L8 R18 R21 R66 R67 R68 R69 R70 R71 SB2 SB4 SB15 SB16 U12 Z1 ZZ1
component class U_Peripherals: B1 B2 C86 C87 C92 CN14 LD5 LD6 P1 P2 R29 R47 R48 R89 R90 R91 R92 R93 R94 R95 R96 R97 R102 SB25 SB27 SB28 SB29 SB33 SB34 U20
component class U_PSRAM: C63 C71 R63 R64 R65 R100 U10
component class U_QSPI: C13 R30 U5 U6
component class U_ST_LINK_V2-1: C1 C3 C4 C5 C6 C7 C8 C9 C10 C11 C12 C14 C15 C16 C17 C57 C68 C74 C81 C82 C83 CN1 CN2 CN3 CN6 CN8 CN9 D1 D2 D3 D4 D5 HW12 LD2 LD3 LD4 R1 R2 R3 R4 R5 R6 R7 R8 R9 R10 R11 R13 R14 R15 R17 R19 R20 R22 R23 R24 R25 R26 R28 R32 R38 R40 SB3 SB6 SB7 SB8 SB9 SB10 SB11 SB12 SB13 T3 U1 U2 U3 U4 U9 U11 U21 X1
component class U_STM32F7: C34 C36 C37 C38 C39 C40 C44 C45 C46 C47 C48 C49 C51 C52 C53 C54 C55 C56 C58 C59 C60 C61 C62 C64 C65 C66 C93 JP1 L1 R27 R36 R37 R42 R43 R44 R45 R49 R50 R51 R52 R54 R55 R56 R57 R59 R60 R61 R62 R101 TP3 TP4 TP5 TP6 TP7 TP8 TP11 TP12 TP13 TP14 TP15 U8 X2 X3
component class U_USB_OTG_FS: C77 CN18 LD9 LD10 R72 R73 R76 R77 R79 R83 R84 R99 T2 U14 U22 U23 U24
component class U_USB_OTG_HS: C78 CN19 LD7 LD8 R16 R74 R75 R78 R80 R81 R82 R98 T1 U13 U15
differential pair USB_STLK_CN: +USB_STLK_CN_P -USB_STLK_CN_N
differential pair USB_OTGHS_CN: +USB_OTGHS_CN_P -USB_OTGHS_CN_N
differential pair USB_OTGHS: +USB_OTGHS_P -USB_OTGHS_N
differential pair USB_OTGFS_CN: +USB_OTGFS_CN_P -USB_OTGFS_CN_N
differential pair USB_OTGFS: +USB_OTGFS_P -USB_OTGFS_N
differential pair SPKOUTL: +NETCN10_1 -NETCN10_2
differential pair SPKOUTR: +NETCN7_1 -NETCN7_2
differential pair USB_STLK: +USB_STLK_P -USB_STLK_N

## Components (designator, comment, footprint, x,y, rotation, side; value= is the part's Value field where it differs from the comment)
B1 "SW-PUSH-CMS_EVQP2_BLUE" TACT_4SM_3R5X5R5 2969,1788 r270 bottom
B2 "SW-PUSH-CMS_EVQP2_BLACK" TACT_4SM_3R5X5R5 2969,1267 r270 bottom
C1 "100nF" 0402C 1680,3285 r90 top
C2 "100nF" 0402C 742.84,3215.76 r180 bottom
C3 "1uF" 0603C 2260,3210 r0 top
C4 "10pF" 0402C 1530,3085 r0 top
C5 "100nF" 0402C 2595,3050 r180 top
C6 "10pF" 0402C 1530,3035 r0 top
C7 "100nF" 0402C 1530,2985 r0 top
C8 "10nF_X7R_10%_0603" 0603C 2325,2935 r0 top
C9 "1uF" 0603C 2615,2930 r180 top
C10 "100nF" 0402C 2615,2870 r180 top
C11 "1uF" 0603C 2295,2835 r90 top
C12 "100nF" 0402C 2350,2835 r90 top
C13 "100nF" 0402C 1405,2805 r180 top
C14 "100nF" 0402C 2615,2735 r180 top
C15 "1uF" 0603C 2345,2670 r270 top
C16 "100nF" 0402C 2400,2665 r270 top
C17 "1uF" 0603C 2620,2635 r180 top
C18 "1uF" 0603C 420,2570 r90 top
C19 "4.7uF" 0603C 475,2570 r270 top
C20 "4.7uF" 0603C 530,2570 r90 top
C21 "4.7uF" 0603C 580,2570 r90 top
C22 "4.7uF" 0603C 630,2570 r90 top
C23 "100nF" 0402C 690,2570 r90 top
C24 "1uF" 0603C 740,2570 r90 top
C25 "2.2uF_X5R_10%_0603" 0603C 800,2570 r90 top
C26 "2.2uF_X5R_10%_0603" 0603C 825,2485 r0 top
C27 "1uF" 0603C 364,2570 r90 top
C28 "2.2uF_X5R_10%_0603" 0603C 825,2425 r0 top
C29 "4.7uF" 0603C 385,2385 r0 top
C30 "100nF" 0402C 810,2370 r0 top
C31 "4.7uF" 0603C 385,2330 r0 top
C32 "100nF" 0402C 810,2330 r0 top
C33 "100nF" 0402C 395,2280 r180 top
C34 "4.7uF" TAN-A 1630,2205 r270 top
C35 "1uF" 0603C 385,2145 r0 top
C36 "100nF" 0402C 1115,2145 r270 top
C37 "100nF" 0402C 1170,2145 r270 top
C38 "100nF" 0402C 1405,2145 r270 top
C39 "100nF" 0402C 1555,2145 r270 top
C40 "100nF" 0402C 1705,2145 r270 top
C41 "100nF" 0402C 467,2126 r270 top
C42 "100nF" 0402C 517,2126 r270 top
C43 "1uF" 0603C 682,2111 r90 top
C44 "100nF" 0402C 1090,2070 r0 top
C45 "100nF" 0402C 1725,2055 r180 top
C46 "100nF" 0402C 1090,2025 r0 top
C47 "100nF" 0402C 1085,1965 r0 top
C48 "4.7pF_NPO_-+0.25pF_0402" 0402C 975,1950 r270 top
C49 "2.2uF" 1206C 1780,1915 r180 top
C50 "1uF" 0603C 2415,1890 r270 top
C51 "4.7pF_NPO_-+0.25pF_0402" 0402C 975,1870 r90 top
C52 "100nF" 0402C 1734,1841 r180 top
C53 "100nF" 0402C 1085,1765 r0 top
C54 "2.2uF_X5R_10%_0603" 0603C 1845,1785 r0 top
C55 "100nF" 0402C 885,1755 r90 top
C56 "100nF" 0402C 1735,1655 r180 top
C57 "10uF" 0603C 106.8,1740 r90 top
C58 "2.2uF" 1206C 1780,1543 r180 top
C59 "100nF" 0402C 1090,1520 r0 top
C60 "100nF" 0402C 1210,1520 r180 top
C61 "100nF" 0402C 1419,1505 r90 top
C62 "100nF" 0402C 1655,1505 r90 top
C63 "100nF" 0402C 1850,1480 r180 top
C64 "1uF" TAN-A 1035,1450 r0 top
C65 "1uF" TAN-A 1245,1450 r180 top
C66 "4.7uF" TAN-A 1505,1450 r90 top
C67 "10uF_POL_10%_TANA" TAN-A 1025,1135 r180 top
C68 "10uF" 0805C 106.8,1310 r90 top
C69 "100nF" 0402C 1060,1065 r180 top
C70 "100nF" 0402C 1061,1015 r180 top
C71 "100nF" 0402C 1815,985 r0 top
C72 "10nF_X7R_10%_0603" 0603C 1065,965 r180 top
C73 "4.7uF_X7R_10%_1206" 1206C 1030,890 r180 top
C74 "10uF" 0805C 340,1100 r0 top
C75 "4.7uF_X7R_10%_1206" 1206C 895,480 r180 top
C76 "10nF_X7R_10%_0603" 0603C 910,405 r180 top
C77 "4.7uF" 0603C 2315,310 r0 top
C78 "4.7uF" 0603C 1455,305 r0 top
C79 "100nF" 0402C 908.74,3410 r90 bottom
C80 "100nF" 0402C 325,3410 r90 bottom
C81 "100nF" 0402C 1970,3100 r90 bottom
C82 "100nF" 0402C 1705,2995 r270 bottom
C83 "100nF" 0402C 1880,2855 r0 bottom
C84 "100nF" 0402C 908.74,2825 r90 bottom
C85 "100nF" 0402C 325,2825 r90 bottom
C86 "100nF" 0402C 2970,1675 r270 bottom
C87 "100nF" 0402C 3065,1390 r270 bottom
C92 "1uF" 0603C 1720,2600 r0 top
C93 "100nF" 0402C 975,1610 r0 top
CN1 "1050170001" MICRO_USB_B_105017 2065.35,3659.44 r180 top
CN2 "Header 4" HDR_1X4_2R54 2775.41,3716.23 r180 top
CN3 "WF25402-06421" HDR_1X2_2R54_RA_11R35 2647.2,3429.41 r90 top locked
CN4 "PJ3028B-3_BE_3PINS" PJ3028B 603.15,3596.61 r270 top
CN5 "PJ3028B-3_GR_3PINS" PJ3028B 1147.16,3596.61 r270 top
CN6 "JP2" SIP2 1800,2735 r0 top
CN7 "JP2" SIP2 205,2345 r180 top
CN8 "Header M Straight 5x2H TSM" TSM-105-01-S-DV 2962,1528 r270 top
CN9 "TC2050-IDC-NL" TC2050-IDC-NL 2205,2275 r270 top
CN10 "JP2" SIP2 205,2185 r180 top
CN11 "BL 1-10 G" HDR_1X10_2R54_W 2509.84,1063.94 r90 top
CN12 "BL 1-8 G" HDR_1X8_2R54_W 609.84,1603.94 r270 top
CN13 "BL 1-8 G" HDR_1X8_2R54_W 2509.84,203.94 r90 top locked
CN14 "Header F Straight 4x2H" HDR_2X4_2R54 432.99,815 r0 bottom
CN15 "BL 1-6 G" HDR_1X6_2R54_W 609.84,703.94 r270 top
CN16 "DF37NB-10DS-0.4V(51)" DF37NB-10DS-0R4V 927.74,3148.16 r270 bottom
CN17 "FH26W-29S-0.3SHW(60)" FH26-29S-0R3SHW 1808.15,633 r180 bottom
CN18 "475900001" MOLEX_47590001 2070.87,162.8 r0 bottom
CN19 "475900001" MOLEX_47590001 1125.98,162.8 r0 bottom
D1 "BAT60JFILM" SOD-323 1795,3670 r90 top
D2 "BAT60JFILM" SOD-323 2694,1312 r0 top
D3 "BAT60JFILM" SOD-323 2694,1425 r0 top
D4 "BAT60JFILM" SOD-323 2694,1530 r0 top
D5 "BAT60JFILM" SOD-323 2694,1630 r0 top
H1 "POSITION HOLE C6D3R5" HOLE_C6D3R5 3001.99,3670.59 r0 top
H2 "POSITION HOLE C6D3R5" HOLE_C6D3R5 167.34,3670.59 r0 top
H4 "POSITION HOLE C6D3R5" HOLE_C6D3R5 3001.99,167.33 r0 top
JP1 "JP2" SIP2 2175,2715 r270 top
L1 "FCM1608KF-601T03" 0603L 1290,1355 r180 top
L2 "FCM1608KF-601T03" 0603L 855,1135 r0 top
L3 "FCM1608KF-601T03" 0603L 855,1055 r0 top
L4 "FCM1608KF-601T03" 0603L 955,1025 r270 top
L5 "FCM1608KF-601T03" 0603L 1195,890 r180 top
L6 "4.7uH 1A 30%" 1210L 1055,745 r270 top
L7 "FCM1608KF-601T03" 0603L 1070,520 r180 top
L8 "FCM1608KF-601T03" 0603L 1070,465 r0 top
LD1 "LED blue" 0603D 120,1855 r180 bottom
LD2 "LED red" 0603D 1615,3685 r90 top
LD3 "LED red" 0603D 2350,3695.59 r90 top
LD4 "LD_BICOLOR_CMS" LED2_3528 1470,3670 r180 top
LD5 "LED red" 0603D 120,2035 r180 bottom
LD6 "LED green" 0603D 120,1945 r180 bottom
LD7 "LED red" 0603D 1490,120 r90 bottom
LD8 "LED green" 0603D 1565,120 r90 bottom
LD9 "LED green" 0603D 2325,120 r90 bottom
LD10 "LED red" 0603D 2400,120 r90 bottom
P1 "SQT-110-01-F-D-RA" SQT-110-01-F-D-RA 2865,2814.96 r90 bottom
P2 "SSW-106-02-F-D-RA" SSW-106-02-F-D-RA 2709.33,370.63 r90 bottom
R1 "1K" 0402R 1670,3665 r270 top
R2 "1K" 0402R 2330,3610.59 r180 top
R3 "100K_1%_0402" 0402R 1765,3285 r270 top
R4 "2K7" 0402R 1810,3285 r90 top
R5 "0" 0402R 1850,3285 r90 top
R6 "4K7_1%_0402" 0402R 1890,3285 r270 top
R7 "100" 0402R 1930,3285 r270 top
R8 "36K" 0402R 1970,3285 r90 top
R9 "100K_1%_0402" 0402R 1980,3540.59 r90 top
R10 "1K5" 0402R 2022.6,3375 r0 top
R11 "10K" 0402R 2035,3285 r90 top
R12 "680_1%_0402" 0402R 240,1855 r0 bottom
R13 "330" 0402R 1440,3520 r90 top
R14 "330" 0402R 1500,3520 r90 top
R15 "100K_1%_0402" 0402R 2400,3210 r180 top
R16 "47K_1%_0402" 0402R 1475,525 r0 top
R17 "10K" 0402R 1530,3170 r0 top
R18 "100K_1%_0402" 0402R 946.84,2999.76 r0 bottom
R19 "10K" 0402R 1530,3130 r0 top
R20 "10K" 0402R 2215,3075 r90 top
R21 "100K_1%_0402" 0402R 742.84,3170.76 r0 bottom
R22 "2K2" 0402R 2595,3000 r0 top
R23 "100" 0402R 2025,2935 r270 top
R24 "100K_1%_0402" 0402R 1550,2920 r270 top
R25 "4K7_1%_0402" 0402R 1530,2845 r0 top
R26 "4K7_1%_0402" 0402R 1530,2805 r0 top
R27 "0_5%_0603" 0603R-GS 2275,2665 r270 top
R28 "22R" R0603 2005,2455 r180 top
R29 "10K" 0402R 1675,2410 r180 top
R30 "10K" 0402R 1405,2380 r0 top
R31 "20" 0402R 895,2370 r0 top
R32 "22R" R0603 2005,2340 r180 top
R33 "20" 0402R 895,2330 r0 top
R35 "0" 0402R 810,2265 r180 top
R36 "10K" 0402R 1260,2250 r270 top
R37 "10K" 0402R 1360,2250 r270 top
R38 "22R" R0603 2005,2220 r180 top
R39 "0" 0402R 807,2201 r180 top
R40 "22R" R0603 2005,2160 r180 top
R41 "10K" 0402R 810,2155 r180 top
R42 "2K7" 0402R 1220,2145 r270 top
R43 "10K" 0402R 1265,2145 r270 top
R44 "2K7" 0402R 1310,2145 r270 top
R45 "10K" 0402R 1355,2145 r270 top
R46 "10K" 0402R 562,2126 r270 top
R47 "1K_1%_0603" 0603R 240,2035 r180 bottom
R48 "510_1%_0603" 0603R 240,1945 r180 bottom
R49 "0" 0402R 1080,1915 r0 top
R50 "0" 0402R 1080,1875 r0 top
R51 "100" 0402R 1085,1805 r0 top
R52 "2K7" 0402R 1845,1830 r180 top
R53 "0" 0402R 2415,1785 r90 top
R54 "3K" 0402R 1845,1740 r0 top
R55 "10K" 0402R 970,1655 r180 top
R56 "2K7" 0402R 1845,1655 r0 top
R57 "10K" 0402R 1090,1650 r180 top
R58 "1K" 0402R 740,1605 r0 top
R59 "2K7" 0402R 975,1550 r180 top
R60 "2K7" 0402R 1090,1605 r180 top
R61 "10K" 0402R 1090,1560 r0 top
R62 "0_5%_0603" 0603R-GS 1145,1355 r0 top
R63 "10K_1%_0603" 0603R 1955,955 r270 top
R64 "0_5%_0603" 0603R-GS 1735,950 r90 top
R65 "0_5%_0603" 0603R-GS 2020,950 r90 top
R66 "10_1%_0603" 0603R 850,895 r270 top
R67 "100K_1%_0402" 0402R 905,890 r270 top
R68 "100K_1%_0402" 0402R 1995,685 r0 top
R69 "100K_1%_0402" 0402R 1070,625 r180 top
R70 "100K_1%_0402" 0402R 1995,620 r0 top
R71 "100K_1%_0402" 0402R 1070,575 r180 top
R72 "0_5%_0603" 0603R-GS 2360,570 r270 top
R73 "47K_1%_0402" 0402R 2425,560 r270 top
R74 "47K_1%_0402" 0402R 1645,485 r90 top
R75 "100K_1%_0402" 0402R 1690,485 r90 top
R76 "10K" 0402R 1800,485 r270 top
R77 "47K_1%_0402" 0402R 1845,485 r90 top
R78 "0" 0402R 1560,450 r90 top
R79 "47K_1%_0402" 0402R 2425,395 r90 top locked
R80 "3K3" 0402R 1560,350 r90 top
R81 "620_1%_0603" 0603R 1490,120 r270 top
R82 "330_1%_0603" 0603R 1565,120 r90 top
R83 "330_1%_0603" 0603R 2325,120 r90 top
R84 "620_1%_0603" 0603R 2400,120 r90 top
R85 "10K" 0402R 793.74,3325 r0 bottom
R86 "10K" 0402R 210,3325 r0 bottom
R89 "10K" 0402R 3065,1675 r90 bottom
R90 "10K" 0402R 3015,1675 r90 bottom
R91 "10K" 0402R 3015,1390 r90 bottom
R92 "1K" 0402R 263,1031 r270 bottom
R93 "10K" 0402R 213,1031 r90 bottom
R94 "10K" 0402R 363,1031 r90 bottom
R95 "10K" 0402R 313,1031 r90 bottom
R96 "10K" 0402R 158,1031 r90 bottom
R97 "1K" 0402R 413,1031 r90 bottom
R98 "0_5%_0805" 0805R 1235,315 r90 bottom
R99 "0_5%_0603" 0603R-GS 1925,335 r180 bottom
R100 "10K_1%_0603" 0603R 1870,930 r0 top
R101 "0" 0402R 1895,695 r180 top
R102 "10K" 0402R 1620,2600 r0 top
SB1 "Solder Bridge ON" JP2_SMD 225,2575 r90 top
SB2 "Solder Bridge OFF" JP2_SMD 914.84,2930.76 r270 bottom
SB3 "Solder Bridge OFF" JP2_SMD 2580,3155 r270 top
SB4 "Solder Bridge ON" JP2_SMD 987.84,2930.76 r270 bottom
SB5 "Solder Bridge OFF" JP2_SMD 295,2575 r90 top
SB6 "Solder Bridge OFF" JP2_SMD 1495,2920 r90 top
SB7 "Solder Bridge ON" JP2_SMD 2615,2805 r180 top
SB8 "Solder Bridge ON" JP2_SMD 1625,2740 r90 top
SB9 "Solder Bridge ON" JP2_SMD 1695,2740 r90 top
SB10 "Solder Bridge ON" JP2_SMD 1900,2455 r0 top
SB11 "Solder Bridge ON" JP2_SMD 1900,2340 r0 top
SB12 "Solder Bridge ON" JP2_SMD 1900,2240 r0 top
SB13 "Solder Bridge ON" JP2_SMD 1900,2160 r0 top
SB14 "Solder Bridge ON" JP2_SMD 2415,1580 r270 top
SB15 "Solder Bridge ON" JP2_SMD 1910,640 r180 top
SB16 "Solder Bridge OFF" JP2_SMD 1910,570 r180 top
SB25 "Solder Bridge ON" JP2_SMD 2730,2935 r0 bottom
SB27 "Solder Bridge ON" JP2_SMD 2735,3165 r0 bottom
SB28 "Solder Bridge ON" JP2_SMD 2730,2580 r180 bottom
SB29 "Solder Bridge ON" JP2_SMD 2730,2739 r180 bottom
SB33 "Solder Bridge ON" JP2_SMD 2905,1670 r270 bottom
SB34 "Solder Bridge ON" JP2_SMD 2905,1385 r270 bottom
SB35 "Solder Bridge ON" JP2_SMD 780,320 r270 bottom
SB36 "Solder Bridge OFF" JP2_SMD 710,320 r270 bottom
SB37 "Solder Bridge ON" JP2_SMD 785.2,174.86 r270 bottom
SB38 "Solder Bridge OFF" JP2_SMD 715.2,174.86 r270 bottom
T1 "9013-SOT23" SOT-23 1690,380 r180 top
T2 "9013-SOT23" SOT-23 1845,380 r180 top
T3 "9013-SOT23" SOT-23 2000,3220 r90 bottom
TP1 "TP" TP_C40 295,2455 r180 top
TP2 "TP" TP_C40 295,2365 r180 top
TP3 "TP" TP_C40 1310,2255 r0 top
TP4 "TP" TP_C40 1465,2255 r0 top
TP5 "TP" TP_C40 1460,2145 r0 top
TP6 "TP" TP_C40 615,2140 r0 top
TP7 "TP" TP_C40 740,2140 r0 top
TP8 "TP" TP_C40 1045,2210 r0 top
TP11 "TP" TP_C40 615,2070 r0 top
TP12 "TP" TP_C40 740,2070 r0 top
TP13 "TP" TP_C40 910,2050 r0 top
TP14 "TP" TP_C40 980,2050 r0 top
TP15 "TP" TP_C40 1080,1700 r0 top
U1 "ST890CDR" SOIC8_1R27_4R9X6 2390,3075 r270 top
U2 "STM32F103CBT6" LQFP48_0R5_9X9 1795,3025 r0 top
U3 "LD3985M33R" SOT-23-5L 2470,2895 r90 top
U4 "LD39050PU33R" DFN6_0R95_3X3 2495,2700 r180 top
U5 "MX25L51245G (MACRONIX)" SON8_1R27_6X8 1460,2595 r0 top
U6 "MT25QL512ABB1EW9-0SIT" DFN8_1R27_6X8_TP4R6X5R3 1215,2593.3 r0 top
U7 "WM8994ECS/R" BGA72_0R5_4R5X4 605,2340 r90 top
U8 "STM32F723IEK" BGA176_0R65_10X10 1410,1830 r0 top
U9 "LD1117S18TR" SOT-223 285,1763 r270 top
U10 "IS66WV51216EBLL-55BLI" FBGA48_0R75_6X8 1810,1235 r270 top
U11 "LD1117S50TR" SOT-223 285,1315 r270 top
U12 "STLD40DPUR" SON8_0R65_3X3 901,745 r180 top
U13 "STMPS2151STR" SOT23-5 1460,420 r0 top
U14 "STMPS2141STR" SOT23-5 2325,420 r0 top
U15 "ECMF02-4CMX8" QFN8_0R5_2R5X1R2 1114,285 r0 top
U16 "IMP34DT05TR" MP34DT01TR 793.07,3409.41 r270 bottom
U17 "IMP34DT05TR" MP34DT01TR 208.46,3409.41 r270 bottom
U18 "IMP34DT05TR" MP34DT01TR 793.07,2824.8 r270 bottom
U19 "IMP34DT05TR" MP34DT01TR 208.46,2824.8 r270 bottom
U20 "STG3692QTR" QFN16_0R4_2R5X1R7 1665,2505 r180 top
U21 "USBLC6-2SC6" SOT23-6 2080,3490 r180 top
U22 "USBLC6-2SC6" SOT23-6 2055,325 r0 bottom
U23 "ESDALC6V1-1U2" D0201_21 2165,315 r180 bottom
U24 "ESDA7P60-1U1M" DO_2SM_1R6X1_21 1920,270 r0 bottom
X1 "NX3225GD-8.00M" XTAL_2SM_3R2X2R5_H1 1390,3035 r90 top
X2 "NX3215SA-32.768K" XTAL_2SM_3R2X1R5 895,1920 r270 top
X3 "NZ2520SH-25.00M" OSC_4SM_2R5X2 975,1755 r0 top
Z1 "STPS1L40M" DO-216AA 966,590 r0 top

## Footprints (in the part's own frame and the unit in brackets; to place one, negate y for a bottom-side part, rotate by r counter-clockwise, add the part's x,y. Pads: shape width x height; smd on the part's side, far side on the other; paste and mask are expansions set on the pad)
0402C [mil] "0402C"
  rect 22x22 smd: 1(-20,0) 2(20,0)
  silkscreen extent -40,-20 40,20, body extent -35,-14 35,14, height 150
0402R [mil] "0402R"
  rect 22x22 smd: 1(-20,0) 2(20,0)
  silkscreen extent -40,-20 40,20, body extent -35,-14 35,14, height 150
0603C [mil] "0603C"
  rect 35x32 smd: 1(-30,0) 2(30,0)
  TOP pour cut-out: -5,-10 5,-10 5,10 -5,10 -5,-10
  silkscreen extent -57,-25 57,25
0603D [mil] "0603D"
  rect 35x32 smd: 1(-30,0) 2(30,0)
  TOP pour cut-out: -5,-10 5,-10 5,10 -5,10 -5,-10
  silkscreen extent -57,-25 65,25, body extent -50,-20 50,20, height 150
0603L [mil] "0603L"
  rect 35x32 smd: 1(-30,0) 2(30,0)
  silkscreen extent -60,-28 60,28, body extent -50,-19 50,19, height 150
0603R [mil] "0603R"
  rect 31x32 smd: 1(-30,0) 2(30,0)
  TOP pour cut-out: -5,10 -5,-10 5,-10 5,10 -5,10
  silkscreen extent -57,-25 57,25, body extent -50,-20 50,20, height 150
0603R-GS [mil] "0603R-GS"
  rect 49x47 smd mask+2: 1(-30.51,0) 2(30.51,0)
  silkscreen extent -60,-32 60,31, body extent -55,-24 55,24, height 150
0805C [mil] "0805C"
  rect 45x50 smd: 1(-35,0) 2(35,0)
  silkscreen extent -70,-35 70,35
0805R [mil] "0805R"
  rect 40x50 smd: 1(35,0) 2(-35,0)
  silkscreen extent -70,-35 71,35, body extent -65,-25 65,25, height 150
1206C [mil] "1206C"
  rect 46x60 smd: 1(-58,0) 2(58,0)
  silkscreen extent -91,-40 91,40, body extent -81,-30 81,30, height 150
1210L [mil] "1210L"
  rect 46x100 smd: 1(-58,0) 2(58,0)
  silkscreen extent -91,-60 91,60, body extent -83,-53 83,53, height 150
BGA72_0R5_4R5X4 [mm] "BGA72_0R5_4R5X4"
  round 0.249 smd mask+0.051: A1(-2,1.75) A2(-1.5,1.75) A3(-1,1.75) A4(-0.5,1.75) A5(0,1.75) A6(0.5,1.75) A7(1,1.75) A8(1.5,1.75) A9(2,1.75) B1(-2,1.25) B2(-1.5,1.25) B3(-1,1.25) B4(-0.5,1.25) B5(0,1.25) B6(0.5,1.25) B7(1,1.25) B8(1.5,1.25) B9(2,1.25) C1(-2,0.75) C2(-1.5,0.75) C3(-1,0.75) C4(-0.5,0.75) C5(0,0.75) C6(0.5,0.75) C7(1,0.75) C8(1.5,0.75) C9(2,0.75) D1(-2,0.25) D2(-1.5,0.25) D3(-1,0.25) D4(-0.5,0.25) D5(0,0.25) D6(0.5,0.25) D7(1,0.25) D8(1.5,0.25) D9(2,0.25) E1(-2,-0.25) E2(-1.5,-0.25) E3(-1,-0.25) E4(-0.5,-0.25) E5(0,-0.25) E6(0.5,-0.25) E7(1,-0.25) E8(1.5,-0.25) E9(2,-0.25) F1(-2,-0.75) F2(-1.5,-0.75) F3(-1,-0.75) F4(-0.5,-0.75) F5(0,-0.75) F6(0.5,-0.75) F7(1,-0.75) F8(1.5,-0.75) F9(2,-0.75) G1(-2,-1.25) G2(-1.5,-1.25) G3(-1,-1.25) G4(-0.5,-1.25) G5(0,-1.25) G6(0.5,-1.25) G7(1,-1.25) G8(1.5,-1.25) G9(2,-1.25) H1(-2,-1.75) H2(-1.5,-1.75) H3(-1,-1.75) H4(-0.5,-1.75) H5(0,-1.75) H6(0.5,-1.75) H7(1,-1.75) H8(1.5,-1.75) H9(2,-1.75)
  silkscreen extent -2.54,-2.01 2.26,2.29, body extent -2.26,-2.01 2.26,2.01, height 3.81
BGA176_0R65_10X10 [mil] "BGA176_0R65_10X10"
  round 12 smd mask+2: A1(-179.13,179.13) A2(-153.54,179.13) A3(-127.95,179.13) A4(-102.36,179.13) A5(-76.77,179.13) A6(-51.18,179.13) A7(-25.59,179.13) A8(0,179.13) A9(25.59,179.13) A10(51.18,179.13) A11(76.77,179.13) A12(102.36,179.13) A13(127.95,179.13) A14(153.54,179.13) A15(179.13,179.13) B1(-179.13,153.54) B2(-153.54,153.54) B3(-127.95,153.54) B4(-102.36,153.54) B5(-76.77,153.54) B6(-51.18,153.54) B7(-25.59,153.54) B8(0,153.54) B9(25.59,153.54) B10(51.18,153.54) B11(76.77,153.54) B12(102.36,153.54) B13(127.95,153.54) B14(153.54,153.54) B15(179.13,153.54) C1(-179.13,127.95) C2(-153.54,127.95) C3(-127.95,127.95) C4(-102.36,127.95) C5(-76.77,127.95) C6(-51.18,127.95) C7(-25.59,127.95) C8(0,127.95) C9(25.59,127.95) C10(51.18,127.95) C11(76.77,127.95) C12(102.36,127.95) C13(127.95,127.95) C14(153.54,127.95) C15(179.13,127.95) D1(-179.13,102.36) D2(-153.54,102.36) D3(-127.95,102.36) D4(-102.36,102.36) D5(-76.77,102.36) D6(-51.18,102.36) D7(-25.59,102.36) D8(0,102.36) D9(25.59,102.36) D10(51.18,102.36) D11(76.77,102.36) D12(102.36,102.36) D13(127.95,102.36) D14(153.54,102.36) D15(179.13,102.36) E1(-179.13,76.77) E2(-153.54,76.77) E3(-127.95,76.77) E4(-102.36,76.77) E12(102.36,76.77) E13(127.95,76.77) E14(153.54,76.77) E15(179.13,76.77) F1(-179.13,51.18) F2(-153.54,51.18) F3(-127.95,51.18) F4(-102.36,51.18) F6(-51.18,51.18) F7(-25.59,51.18) F8(0,51.18) F9(25.59,51.18) F10(51.18,51.18) F12(102.36,51.18) F13(127.95,51.18) F14(153.54,51.18) F15(179.13,51.18) G1(-179.13,25.59) G2(-153.54,25.59) G3(-127.95,25.59) G4(-102.36,25.59) G6(-51.18,25.59) G7(-25.59,25.59) G8(0,25.59) G9(25.59,25.59) G10(51.18,25.59) G12(102.36,25.59) G13(127.95,25.59) G14(153.54,25.59) G15(179.13,25.59) H1(-179.13,0) H2(-153.54,0) H3(-127.95,0) H4(-102.36,0) H6(-51.18,0) H7(-25.59,0) H8(0,0) H9(25.59,0) H10(51.18,0) H12(102.36,0) H13(127.95,0) H14(153.54,0) H15(179.13,0) J1(-179.13,-25.59) J2(-153.54,-25.59) J3(-127.95,-25.59) J4(-102.36,-25.59) J6(-51.18,-25.59) J7(-25.59,-25.59) J8(0,-25.59) J9(25.59,-25.59) J10(51.18,-25.59) J12(102.36,-25.59) J13(127.95,-25.59) J14(153.54,-25.59) J15(179.13,-25.59) K1(-179.13,-51.18) K2(-153.54,-51.18) K3(-127.95,-51.18) K4(-102.36,-51.18) K6(-51.18,-51.18) K7(-25.59,-51.18) K8(0,-51.18) K9(25.59,-51.18) K10(51.18,-51.18) K12(102.36,-51.18) K13(127.95,-51.18) K14(153.54,-51.18) K15(179.13,-51.18) L1(-179.13,-76.77) L2(-153.54,-76.77) L3(-127.95,-76.77) L4(-102.36,-76.77) L12(102.36,-76.77) L13(127.95,-76.77) L14(153.54,-76.77) L15(179.13,-76.77) M1(-179.13,-102.36) M2(-153.54,-102.36) M3(-127.95,-102.36) M4(-102.36,-102.36) M5(-76.77,-102.36) M6(-51.18,-102.36) M7(-25.59,-102.36) M8(0,-102.36) M9(25.59,-102.36) M10(51.18,-102.36) M11(76.77,-102.36) M12(102.36,-102.36) M13(127.95,-102.36) M14(153.54,-102.36) M15(179.13,-102.36) N1(-179.13,-127.95) N2(-153.54,-127.95) N3(-127.95,-127.95) N4(-102.36,-127.95) N5(-76.77,-127.95) N6(-51.18,-127.95) N7(-25.59,-127.95) N8(0,-127.95) N9(25.59,-127.95) N10(51.18,-127.95) N11(76.77,-127.95) N12(102.36,-127.95) N13(127.95,-127.95) N14(153.54,-127.95) N15(179.13,-127.95) P1(-179.13,-153.54) P2(-153.54,-153.54) P3(-127.95,-153.54) P4(-102.36,-153.54) P5(-76.77,-153.54) P6(-51.18,-153.54) P7(-25.59,-153.54) P8(0,-153.54) P9(25.59,-153.54) P10(51.18,-153.54) P11(76.77,-153.54) P12(102.36,-153.54) P13(127.95,-153.54) P14(153.54,-153.54) P15(179.13,-153.54) R1(-179.13,-179.13) R2(-153.54,-179.13) R3(-127.95,-179.13) R4(-102.36,-179.13) R5(-76.77,-179.13) R6(-51.18,-179.13) R7(-25.59,-179.13) R8(0,-179.13) R9(25.59,-179.13) R10(51.18,-179.13) R11(76.77,-179.13) R12(102.36,-179.13) R13(127.95,-179.13) R14(153.54,-179.13) R15(179.13,-179.13)
  silkscreen extent -276,-276 276,276
D0201_21 [mil] "D0201_21"
  rect 12x12 smd: 1(11.02,0) 2(-11.02,0)
  silkscreen extent -9,-25 7,-15, body extent -18,-9 19,9, height 150
DF37NB-10DS-0R4V [mil] "DF37NB-10DS-0R4V"
  rect 8x27 smd mask+2: 1(-31.5,52.17) 2(-15.75,52.17) 3(0,52.17) 4(15.75,52.17) 5(31.5,52.17) 6(31.5,-52.17) 7(15.75,-52.17) 8(0,-52.17) 9(-15.75,-52.17) 10(-31.5,-52.17)
  rect 16x43 smd: 11(80.31,0) 12(-80.31,0)
  silkscreen extent -95,-46 83,84, body extent -90,-70 91,70, height 150
DFN6_0R95_3X3 [mil] "DFN6_0R95_3X3"
  rect 18x28 smd mask+2: 1(-37.4,-56.52) 2(0,-56.52) 3(37.4,-56.52) 4(37.4,56.52) 5(0,56.52) 6(-37.4,56.52)
  rect 95x65 smd mask+2: 7(0,0)
  silkscreen extent -60,-110 60,60, body extent -59,-72 59,72, height 150
DFN8_1R27_6X8_TP4R6X5R3 [mil] "DFN8_1R27_6X8_TP4R6X5R3"
  rect 22x36 smd: 1(-75,-153.54) 2(-25,-153.54) 3(25,-153.54) 4(75,-153.54) 5(75,153.54) 6(25,153.54) 7(-25,153.54) 8(-75,153.54)
  rect 180x210 smd: 9(0,0)
  silkscreen extent -119,-206 118,157, body extent -120,-175 119,174, height 150
DO-216AA [mil] "DO-216AA"
  rect 45x32 smd: 1(0,0)
  rect 90x89 smd: 2(-90,0)
  silkscreen extent -170,-60 40,60, body extent -165,-55 35,55, height 150
DO_2SM_1R6X1_21 [mil] "DO_2SM_1R6X1_21"
  rect 22x31 smd: 1(24.61,0) 2(-24.61,0)
  silkscreen extent -50,-30 55,70, body extent -39,-19 39,20, height 150
FBGA48_0R75_6X8 [mil] "FBGA48_0R75_6X8"
  round 14 smd mask+2: A1(-73.82,103.35) A2(-44.29,103.35) A3(-14.76,103.35) A4(14.76,103.35) A5(44.29,103.35) A6(73.82,103.35) B1(-73.82,73.82) B2(-44.29,73.82) B3(-14.76,73.82) B4(14.76,73.82) B5(44.29,73.82) B6(73.82,73.82) C1(-73.82,44.29) C2(-44.29,44.29) C3(-14.76,44.29) C4(14.76,44.29) C5(44.29,44.29) C6(73.82,44.29) D1(-73.82,14.76) D2(-44.29,14.76) D3(-14.76,14.76) D4(14.76,14.76) D5(44.29,14.76) D6(73.82,14.76) E1(-73.82,-14.76) E2(-44.29,-14.76) E3(-14.76,-14.76) E4(14.76,-14.76) E5(44.29,-14.76) E6(73.82,-14.76) F1(-73.82,-44.29) F2(-44.29,-44.29) F3(-14.76,-44.29) F4(14.76,-44.29) F5(44.29,-44.29) F6(73.82,-44.29) G1(-73.82,-73.82) G2(-44.29,-73.82) G3(-14.76,-73.82) G4(14.76,-73.82) G5(44.29,-73.82) G6(73.82,-73.82) H1(-73.82,-103.35) H2(-44.29,-103.35) H3(-14.76,-103.35) H4(14.76,-103.35) H5(44.29,-103.35) H6(73.82,-103.35)
  silkscreen extent -197,-236 197,236, body extent -120,-160 120,160, height 150
FH26-29S-0R3SHW [mil] "FH26-29S-0R3SHW"
  rect 12x32 smd: 1(165.35,57.09) 3(141.73,57.09) 5(118.11,57.09) 7(94.49,57.09) 9(70.87,57.09) 11(47.24,57.09) 13(23.62,57.09) 15(0,57.09) 17(-23.62,57.09) 19(-47.24,57.09) 21(-70.87,57.09) 23(-94.49,57.09) 25(-118.11,57.09) 27(-141.73,57.09) 29(-165.35,57.09)
  rect 11x32 smd mask+3: 2(153.54,-57.09) 4(129.92,-57.09) 6(106.3,-57.09) 8(82.68,-57.09) 10(59.06,-57.09) 12(35.43,-57.09) 14(11.81,-57.09) 16(-11.81,-57.09) 18(-35.43,-57.09) 20(-59.06,-57.09) 22(-82.68,-57.09) 24(-106.3,-57.09) 26(-129.92,-57.09) 28(-153.54,-57.09)
  rect 16x37 smd: " "(-192.91,47.24) " "(192.91,47.24)
  silkscreen extent -205,-67 204,117, body extent -202,-78 205,73, height 150
HDR_1X2_2R54_RA_11R35 [mil] "HDR_1X2_2R54_RA_11R35"
  rect 60x60 / inner round 60 / far side rect 60x60 hole 40: 1(0,0)
  round 60 hole 40: 2(-100,0)
  silkscreen extent -200,-504 100,22, body extent -200,-505 100,30, height 150
HDR_1X4_2R54 [mil] "HDR_1X4_2R54"
  rect 52x52 hole 36: 1(0,0)
  round 52 hole 36: 2(100,0) 3(200,0) 4(300,0)
  silkscreen extent -70,-70 355,55, body extent -138,-138 438,138, height 150
HDR_1X6_2R54_W [mil] "HDR_1X6_2R54_W"
  rect 60x60 / inner round 60 / far side rect 60x60 hole 40: 1(0,0)
  round 60 hole 40: 2(100,0) 3(200,0) 4(300,0) 5(400,0) 6(500,0)
  silkscreen extent -65,-65 550,50, body extent -50,-50 550,50, height 150
HDR_1X8_2R54_W [mil] "HDR_1X8_2R54_W"
  rect 60x60 / inner round 60 / far side rect 60x60 hole 40: 1(0,0)
  round 60 hole 40: 2(100,0) 3(200,0) 4(300,0) 5(400,0) 6(500,0) 7(600,0) 8(700,0)
  silkscreen extent -65,-65 750,50, body extent -50,-50 750,50, height 150
HDR_1X10_2R54_W [mil] "HDR_1X10_2R54_W"
  rect 60x60 / inner round 60 / far side rect 60x60 hole 40: 1(0,0)
  round 60 hole 40: 2(100,0) 3(200,0) 4(300,0) 5(400,0) 6(500,0) 7(600,0) 8(700,0) 9(800,0) 10(900,0)
  silkscreen extent -65,-65 950,50, body extent -50,-50 950,50, height 150
HDR_2X4_2R54 [mil] "HDR_2X4_2R54"
  rect 52x52 hole 36: 1(0,0)
  round 52 hole 36: 2(0,-100) 3(-100,0) 4(-100,-100) 5(-200,0) 6(-200,-100) 7(-300,0) 8(-300,-100)
  silkscreen extent -350,-155 65,70, body extent -457,-257 122,157, height 150
HOLE_C6D3R5 [mil] "HOLE_C6D3R5"
  round 236 hole 138: 1(0,0)
  body extent -123,-123 123,123, height 150
JP2_SMD [mil] "JP2_SMD"
  round 6 smd: 1(-23.01,-0.33) 2(15.83,-1.19)
  TOP region: 12.7,22.91 33.91,1.7 32.21,0 33.91,-1.7 12.7,-22.91 2.09,-12.3 4.5,-9.89 -5.39,0 4.5,9.89 2.09,12.3 12.7,22.91
  TOP region: -34.18,2.96 -12.96,24.18 -1.82,13.04 -15.13,-0.26 -2.09,-13.3 -12.7,-23.91 -33.91,-2.7 -31.22,0 -34.18,2.96
  silkscreen extent -40,-30 40,30, body extent -35,-24 35,24, height 150
LED2_3528 [mil] "LED2_3528"
  rect 44x59 smd: 1(-29.53,-59.06) 2(-29.53,59.06) 3(29.53,59.06) 4(29.53,-59.06)
  silkscreen extent -109,-70 65,69, body extent -55,-90 55,90, height 150
LQFP48_0R5_9X9 [mil] "LQFP48_0R5_9X9"
  rect 53x11 smd mask+2: 1(-171.26,108.27) 2(-171.26,88.58) 3(-171.26,68.9) 4(-171.26,49.21) 5(-171.26,29.53) 6(-171.26,9.84) 7(-171.26,-9.84) 8(-171.26,-29.53) 9(-171.26,-49.21) 10(-171.26,-68.9) 11(-171.26,-88.58) 12(-171.26,-108.27) 25(171.26,-108.27) 26(171.26,-88.58) 27(171.26,-68.9) 28(171.26,-49.21) 29(171.26,-29.53) 30(171.26,-9.84) 31(171.26,9.84) 32(171.26,29.53) 33(171.26,49.21) 34(171.26,68.9) 35(171.26,88.58) 36(171.26,108.27)
  rect 11x53 smd mask+2: 13(-108.27,-171.26) 14(-88.58,-171.26) 15(-68.9,-171.26) 16(-49.21,-171.26) 17(-29.53,-171.26) 18(-9.84,-171.26) 19(9.84,-171.26) 20(29.53,-171.26) 21(49.21,-171.26) 22(68.9,-171.26) 23(88.58,-171.26) 24(108.27,-171.26) 37(108.27,171.26) 38(88.58,171.26) 39(68.9,171.26) 40(49.21,171.26) 41(29.53,171.26) 42(9.84,171.26) 43(-9.84,171.26) 44(-29.53,171.26) 45(-49.21,171.26) 46(-68.9,171.26) 47(-88.58,171.26) 48(-108.27,171.26)
  silkscreen extent -220,-220 220,220
MICRO_USB_B_105017 [mil] "MICRO_USB_B_105017"
  rect 16x53 smd: 1(-51.18,2.95) 2(-25.59,2.95) 3(0,2.95) 4(25.59,2.95) 5(51.18,2.95)
  oval 47x75 hole 24 slot 51 at 90 deg: 6(-137.8,-102.36) 7(137.8,-102.36)
  round 59 hole 33: 8(-98.43,3.94) 9(98.43,3.94)
  rect 59x75 smd: 10(-39.37,-102.36) 11(39.37,-102.36)
  Keep-Out Layer lines w1: 220.47,-159.45 -173.23,-159.45
  silkscreen extent -148,-199 148,70, body extent -165,-200 165,35, height 150
MOLEX_47590001 [mil] "MOLEX_47590001"
  rect 16x53 smd: 1(-51.18,0) 2(-25.59,0) 3(0,0) 4(25.59,0) 5(51.18,0)
  oval 42x63 hole 30 slot 33 at 90 deg mask+2: 6(-89.57,-12.8) 7(89.57,-12.8)
  oval 55x75 hole 33 slot 59 at 90 deg: 8(163.39,112.4) 9(-163.39,112.4)
  rect 114x79 smd: 10(0,105.31)
  Keep-Out Layer lines w1: -235,162.8 -110.24,162.8 -110.24,92.52 -106.3,88.58 -80.71,88.58 -76.77,92.52 -76.77,162.8 76.77,162.8 76.77,92.52 80.71,88.58 106.3,88.58 110.24,92.52 110.24,162.8 380,162.8
  silkscreen extent -161,-61 161,216, body extent -190,-45 190,215, height 150
MP34DT01TR [mil] "MP34DT01TR"
  rect 20x42 smd: 1(16.73,-26.57) 2(16.73,26.57) 3(-16.73,26.57) 4(-16.73,-26.57)
  round 6 smd: 5(1,69)
  TOP region: 25.59,61.11 25.59,74.89 -25.59,74.89 -25.59,61.11 25.59,61.11
  TOP region: 54.89,-45.28 54.89,45.28 41.11,45.28 41.11,-45.28 54.89,-45.28
  TOP region: -41.11,-45.28 -41.11,45.28 -54.89,45.28 -54.89,-45.28 -41.11,-45.28
  TOP region: 25.59,-74.89 25.59,-61.11 -25.59,-61.11 -25.59,-74.89 25.59,-74.89
  silkscreen extent -60,-90 70,80, body extent -59,-79 58,79, height 150
OSC_4SM_2R5X2 [mil] "OSC_4SM_2R5X2"
  rect 41x37 smd: 1(-36.42,-28.54) 2(36.42,-28.54) 3(36.42,28.54) 4(-36.42,28.54)
  silkscreen extent -105,-75 70,60, body extent -60,-50 60,50, height 150
PJ3028B [mil] "PJ3028B"
  rect 48x98 smd: 2(-153.54,-157.48) 7(-78.74,157.48)
  rect 79x98 smd: 3(-39.37,-157.48) 4(31.5,157.48) 6(322.83,-157.48)
  rect 98x79 smd: 5(482.28,31.5)
  round 79 hole 79 unplated: " "(0,0) " "(275.59,0)
  silkscreen extent -236,-118 433,118, body extent -235,-210 532,210, height 150
QFN8_0R5_2R5X1R2 [mil] "QFN8_0R5_2R5X1R2"
  oct 1x1 smd mask+2: 1(-29.53,-19.69) 4(29.53,-19.69) 5(29.53,19.69) 8(-29.53,19.69)
  rect 8x24 smd mask+2: 2(-9.84,-19.69) 3(9.84,-19.69) 6(9.84,19.69) 7(-9.84,19.69)
  silkscreen extent -54,-36 54,42, body extent -48,-36 48,36, height 150
QFN16_0R4_2R5X1R7 [mil] "QFN16_0R4_2R5X1R7"
  oval 8x24 smd mask+2: 1(-23.62,-35.62) 2(-7.87,-35.62) 3(7.87,-35.62) 4(23.62,-35.62) 9(23.62,35.62) 10(7.87,35.62) 11(-7.87,35.62) 12(-23.62,35.62)
  oval 24x8 smd mask+2: 5(51.37,-23.62) 6(51.37,-7.87) 7(51.37,7.87) 8(51.37,23.62) 13(-51.37,23.62) 14(-51.37,7.87) 15(-51.37,-7.87) 16(-51.37,-23.62)
  rect 59x28 smd mask+2: 17(0,0)
  silkscreen extent -63,-74 50,40, body extent -65,-50 65,50, height 150
R0603 [mil] "R0603"
  rect 31x32 smd: 1(-30,0) 2(30,0)
  TOP pour cut-out: -5,10 -5,-10 5,-10 5,10 -5,10
  silkscreen extent -57,-25 57,25, body extent -50,-20 50,20, height 150
SIP2 [mil] "SIP2"
  rect 60x60 / inner round 60 / far side rect 60x60 hole 40: 1(0,0)
  round 60 hole 40: 2(100,0)
  silkscreen extent -75,-50 150,50
SOD-323 [mil] "SOD-323"
  rect 32x32 smd: 1(44.29,0) 2(-44.29,0)
  silkscreen extent -50,-35 50,35, body extent -65,-27 65,25, height 150
SOIC8_1R27_4R9X6 [mil] "SOIC8_1R27_4R9X6"
  rect 22x70 smd: 1(-75,-103.3) 2(-25,-103.3) 3(25,-103.3) 4(75,-103.3) 5(75,103.3) 6(25,103.3) 7(-25,103.3) 8(-75,103.3)
  silkscreen extent -100,-173 100,55
SON8_0R65_3X3 [mil] "SON8_0R65_3X3"
  rect 16x31 smd: 1(-38.39,-58.07) 2(-12.8,-58.07) 3(12.8,-58.07) 4(38.39,-58.07) 5(38.39,58.07) 6(12.8,58.07) 7(-12.8,58.07) 8(-38.39,58.07)
  oct 1x1 smd: 9(0,0)
  silkscreen extent -88,-102 65,65, body extent -78,-78 78,78, height 150
SON8_1R27_6X8 [mil] "SON8_1R27_6X8"
  rect 22x36 smd: 1(-75,-153.54) 2(-25,-153.54) 3(25,-153.54) 4(75,-153.54) 5(75,153.54) 6(25,153.54) 7(-25,153.54) 8(-75,153.54)
  rect 181x185 smd: 9(0,0)
  silkscreen extent -127,-194 118,157, body extent -120,-175 119,174, height 150
SOT23-5 [mil] "SOT23-5"
  rect 25x45 smd: 1(-37.4,-47.24) 2(0,-47.24) 3(37.4,-47.24) 4(37.4,47.24) 5(-37.4,47.24)
  silkscreen extent -106,-68 65,35, body extent -57,-70 57,70, height 150
SOT23-6 [mil] "SOT23-6"
  rect 25x53 smd: 1(-37.4,-47.24) 2(0,-47.24) 3(37.4,-47.24) 4(37.4,47.24) 5(0,47.24) 6(-37.4,47.24)
  silkscreen extent -75,-95 65,85, body extent -57,-75 57,75, height 150
SOT-23 [mil] "SOT-23"
  rect 45x25 smd: 1(43.31,-37.4) 2(43.31,37.4) 3(-43.31,0)
  silkscreen extent -35,-60 35,60, body extent -70,-60 70,60, height 150
SOT-23-5L [mil] "SOT-23-5L"
  rect 25x45 smd: 1(-37.4,-47.24) 2(0,-47.24) 3(37.4,-47.24) 4(37.4,47.24) 5(-37.4,47.24)
  silkscreen extent -65,-106 65,35, body extent -57,-70 57,70, height 150
SOT-223 [mil] "SOT-223"
  rect 71x40 smd: 1(124.02,-90.55) 2(124.02,0) 3(124.02,90.55)
  rect 71x130 smd: 4(-124.02,0)
  silkscreen extent -75,-130 204,130, body extent -160,-128 160,128, height 150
